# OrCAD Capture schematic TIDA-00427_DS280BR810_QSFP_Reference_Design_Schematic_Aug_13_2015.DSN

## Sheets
1 1. NOTES: title: TIDA-00427 DS280BR810 QSFP Reference Design; rev: 1
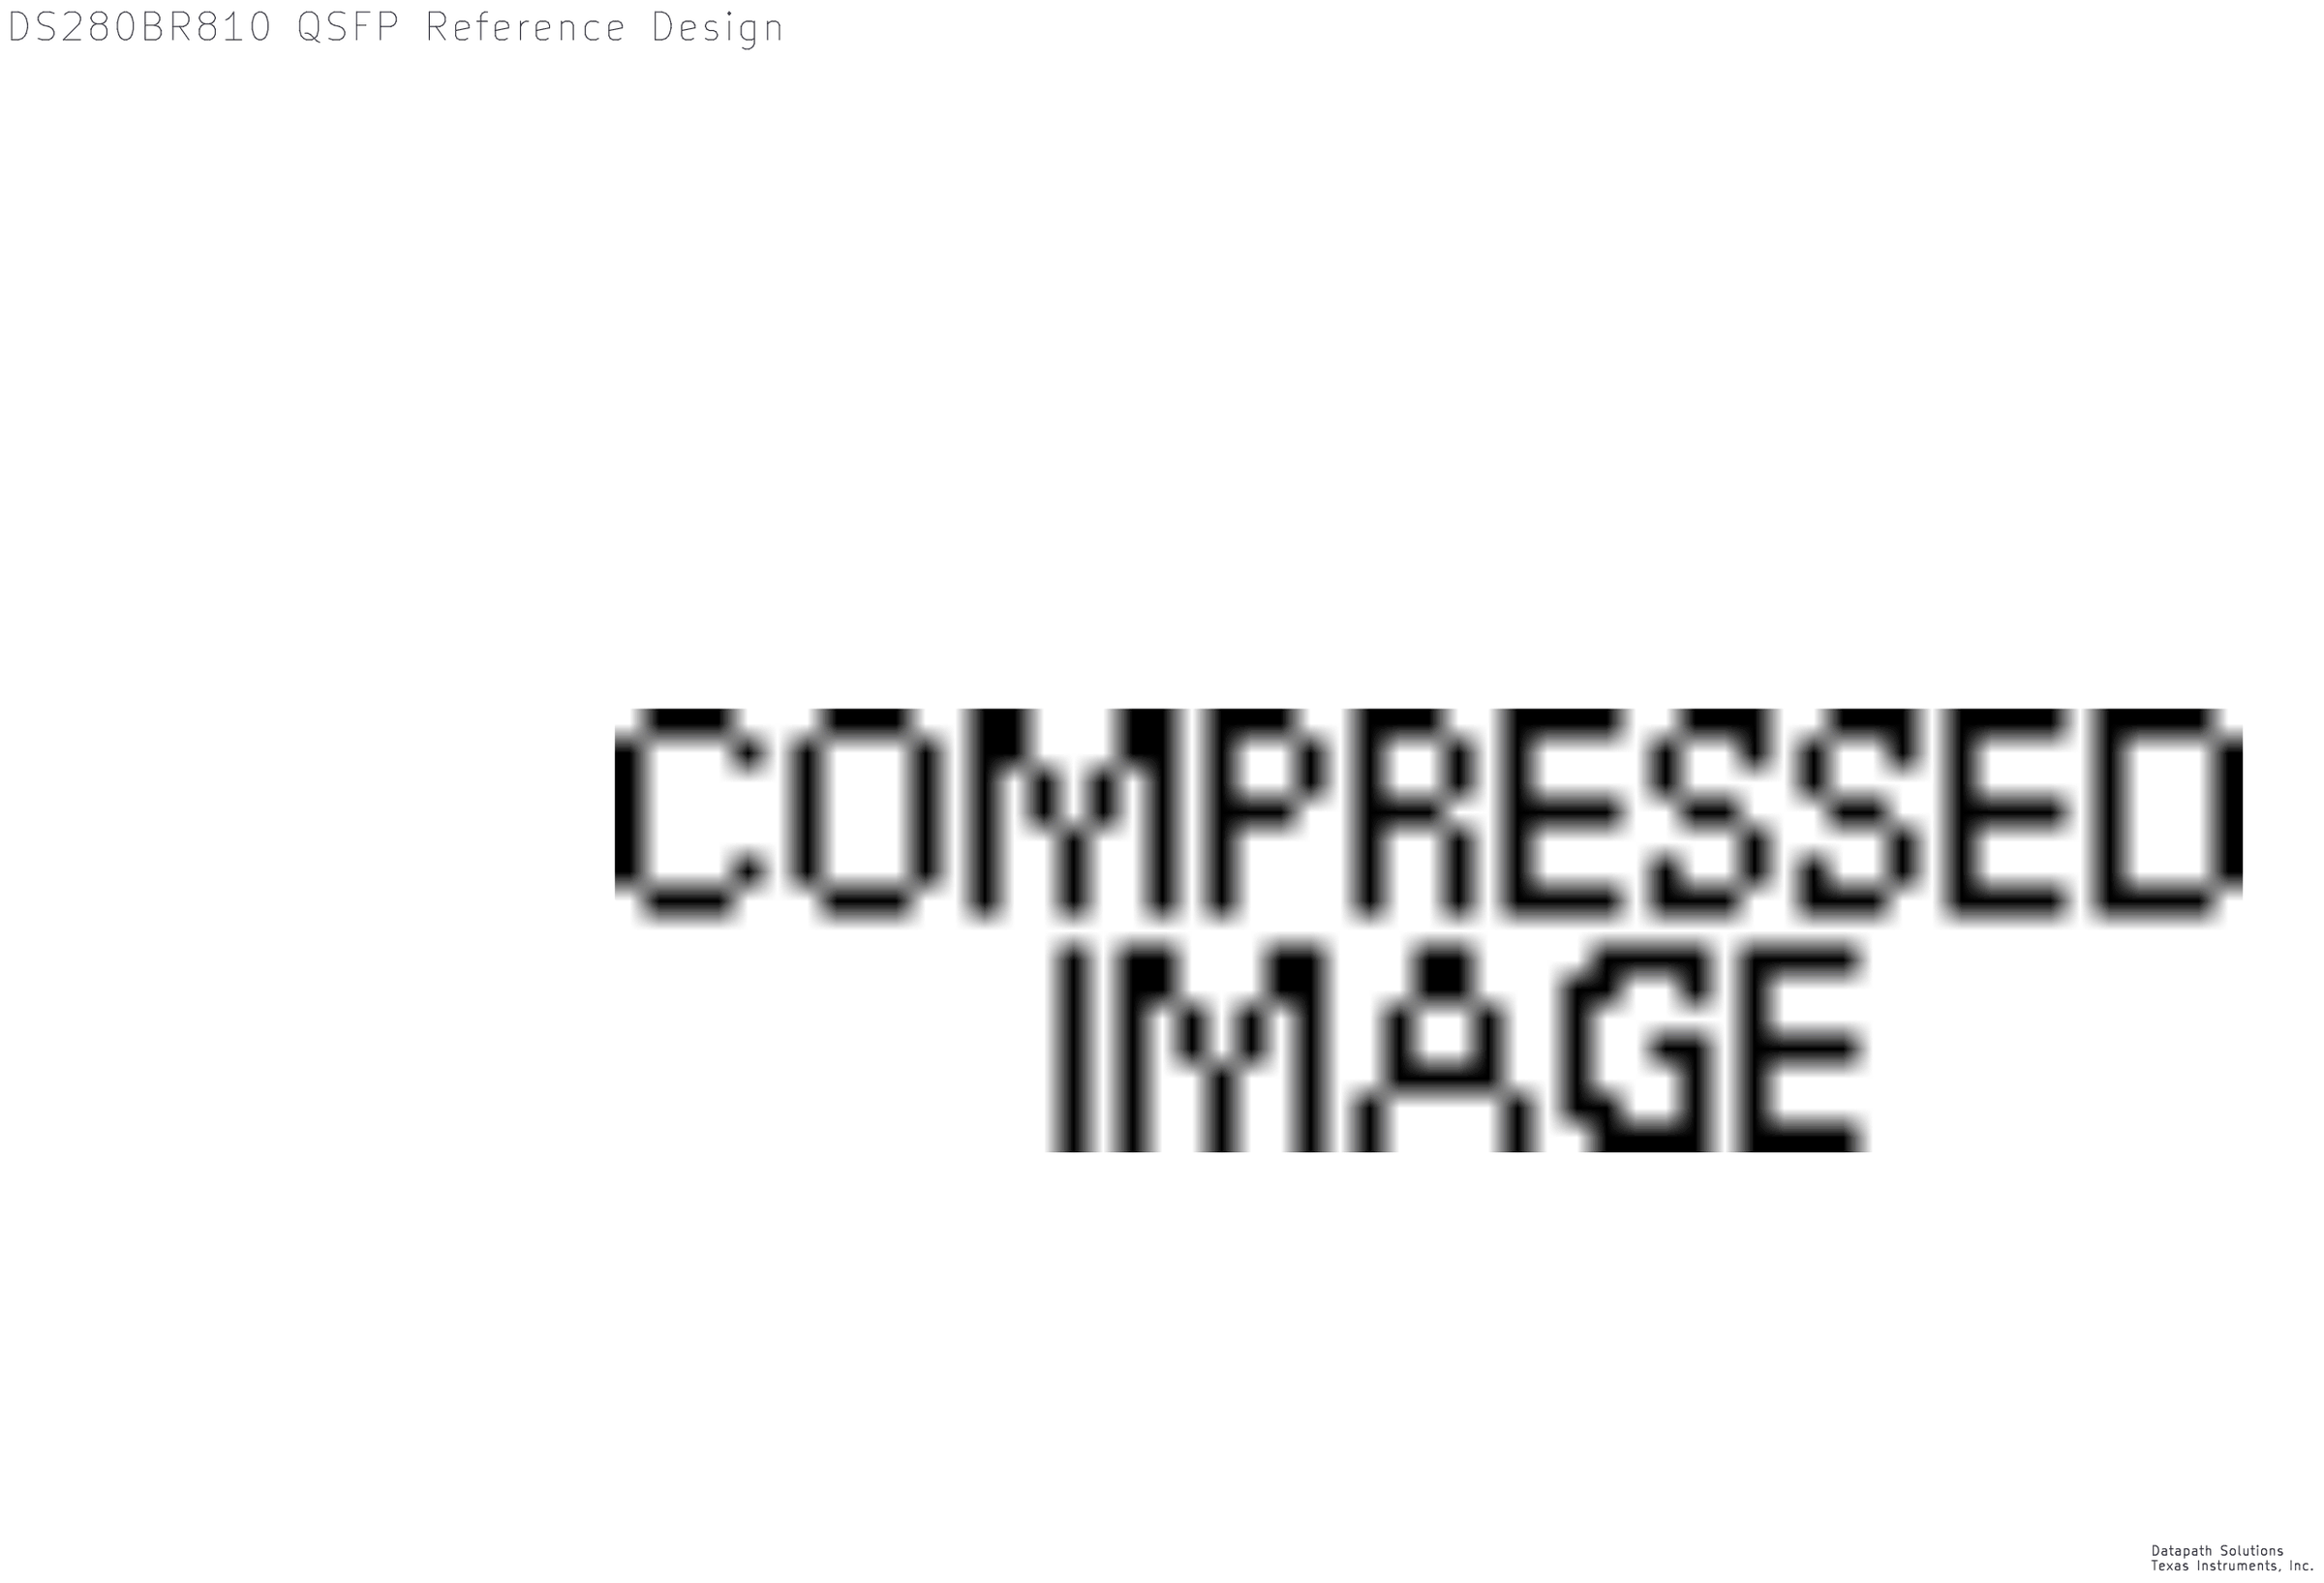
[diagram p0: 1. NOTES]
2 2. DS280BR810_CABLE_2_HOST: size C; note: 305-PD-14-0660
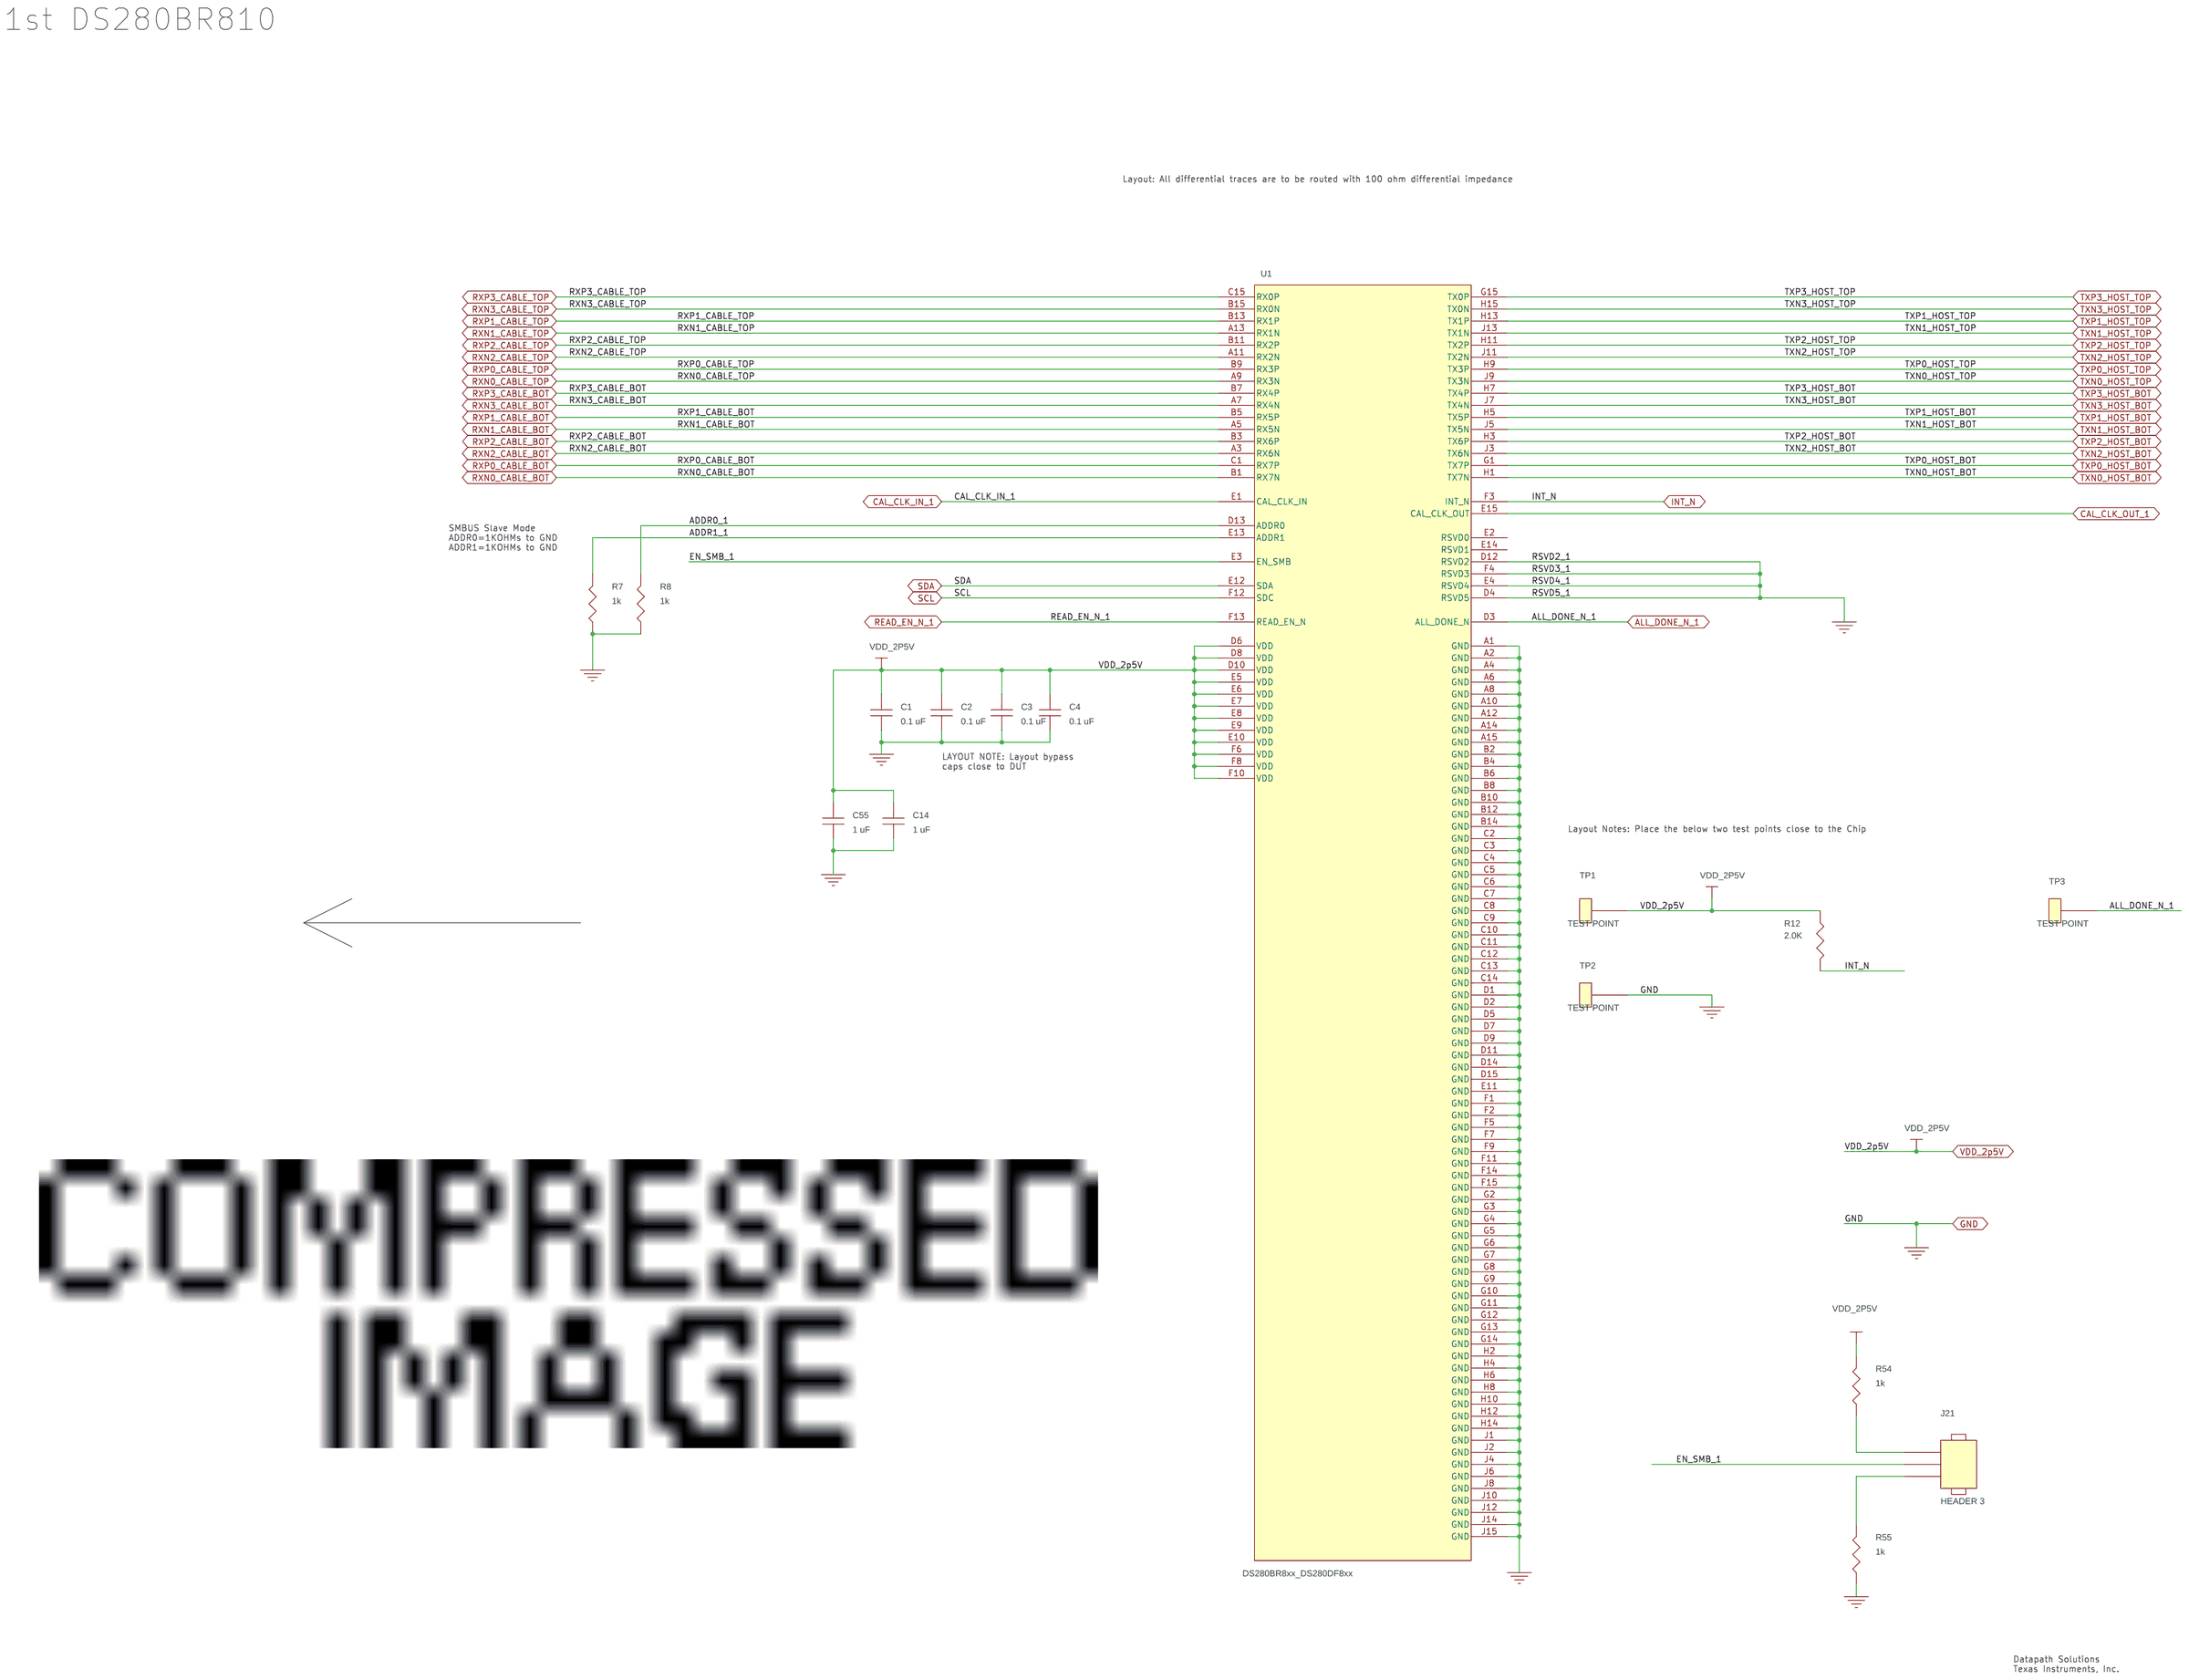
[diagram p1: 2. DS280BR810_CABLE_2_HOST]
3 3. DS280BR810_HOST_2_CABLE: size C; note: 305-PD-14-0660
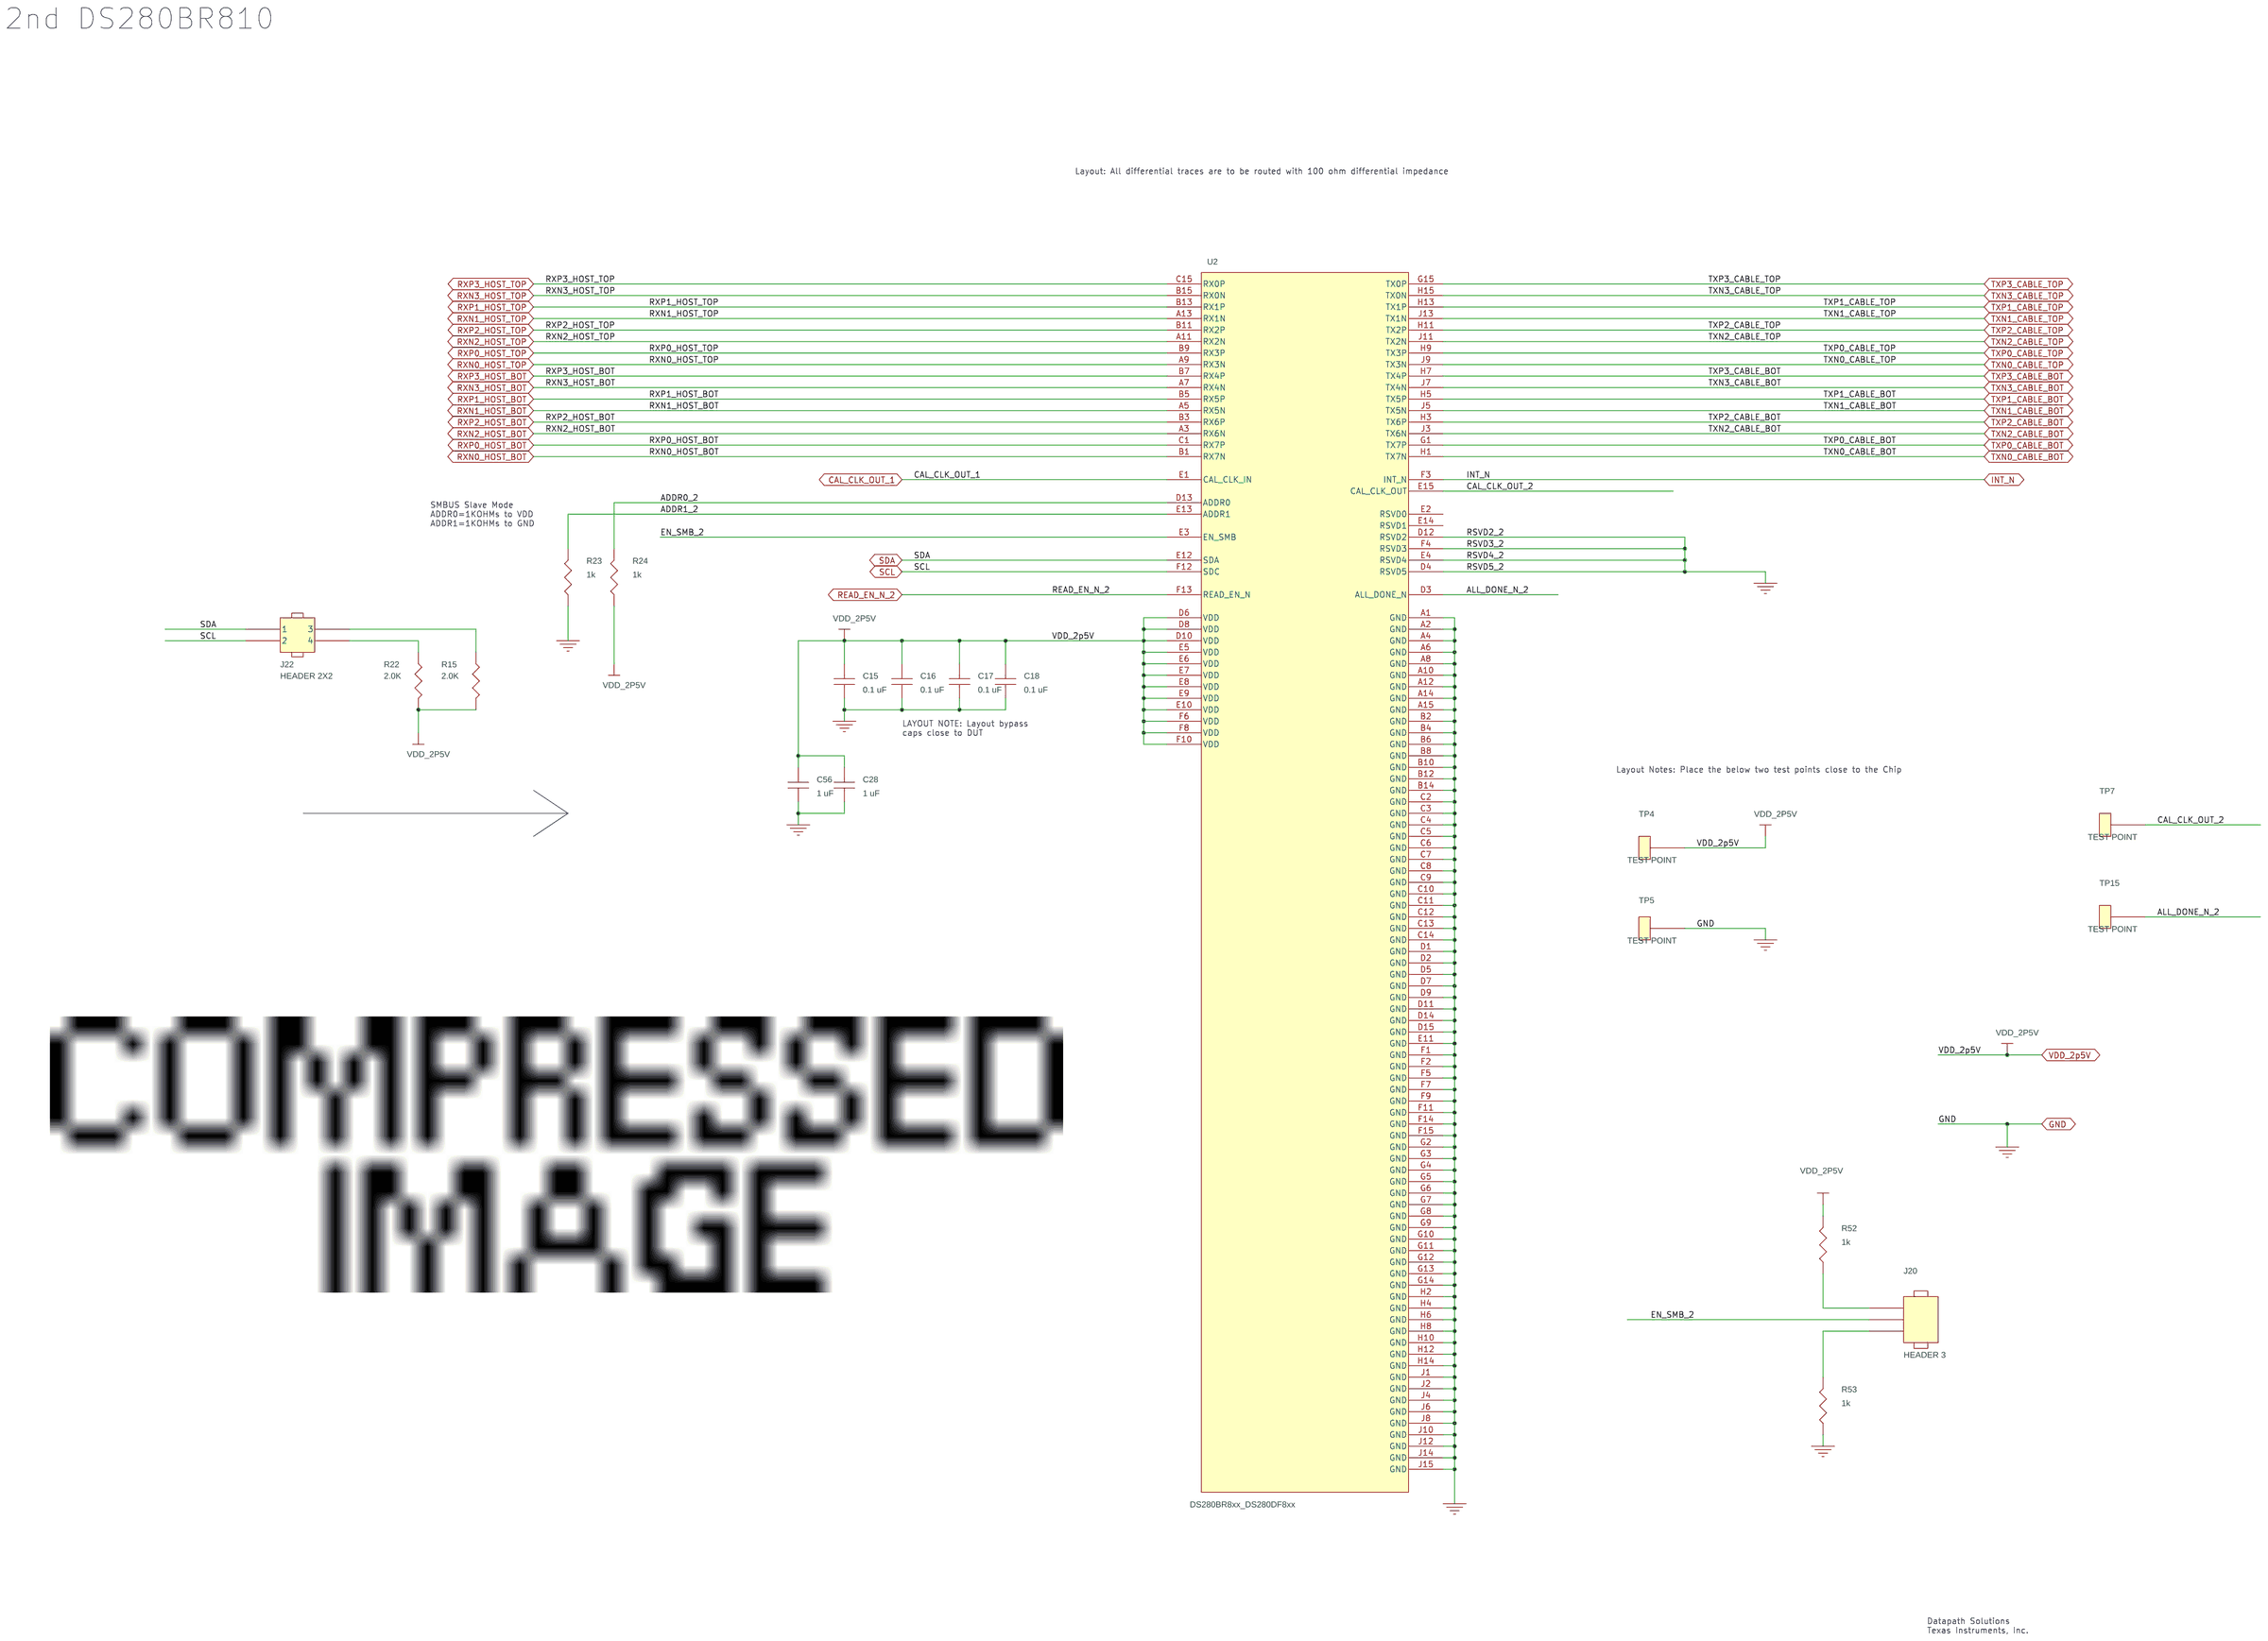
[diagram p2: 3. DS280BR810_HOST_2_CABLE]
4 4. USB2ANY: size B; note: 305-PD-14-0660
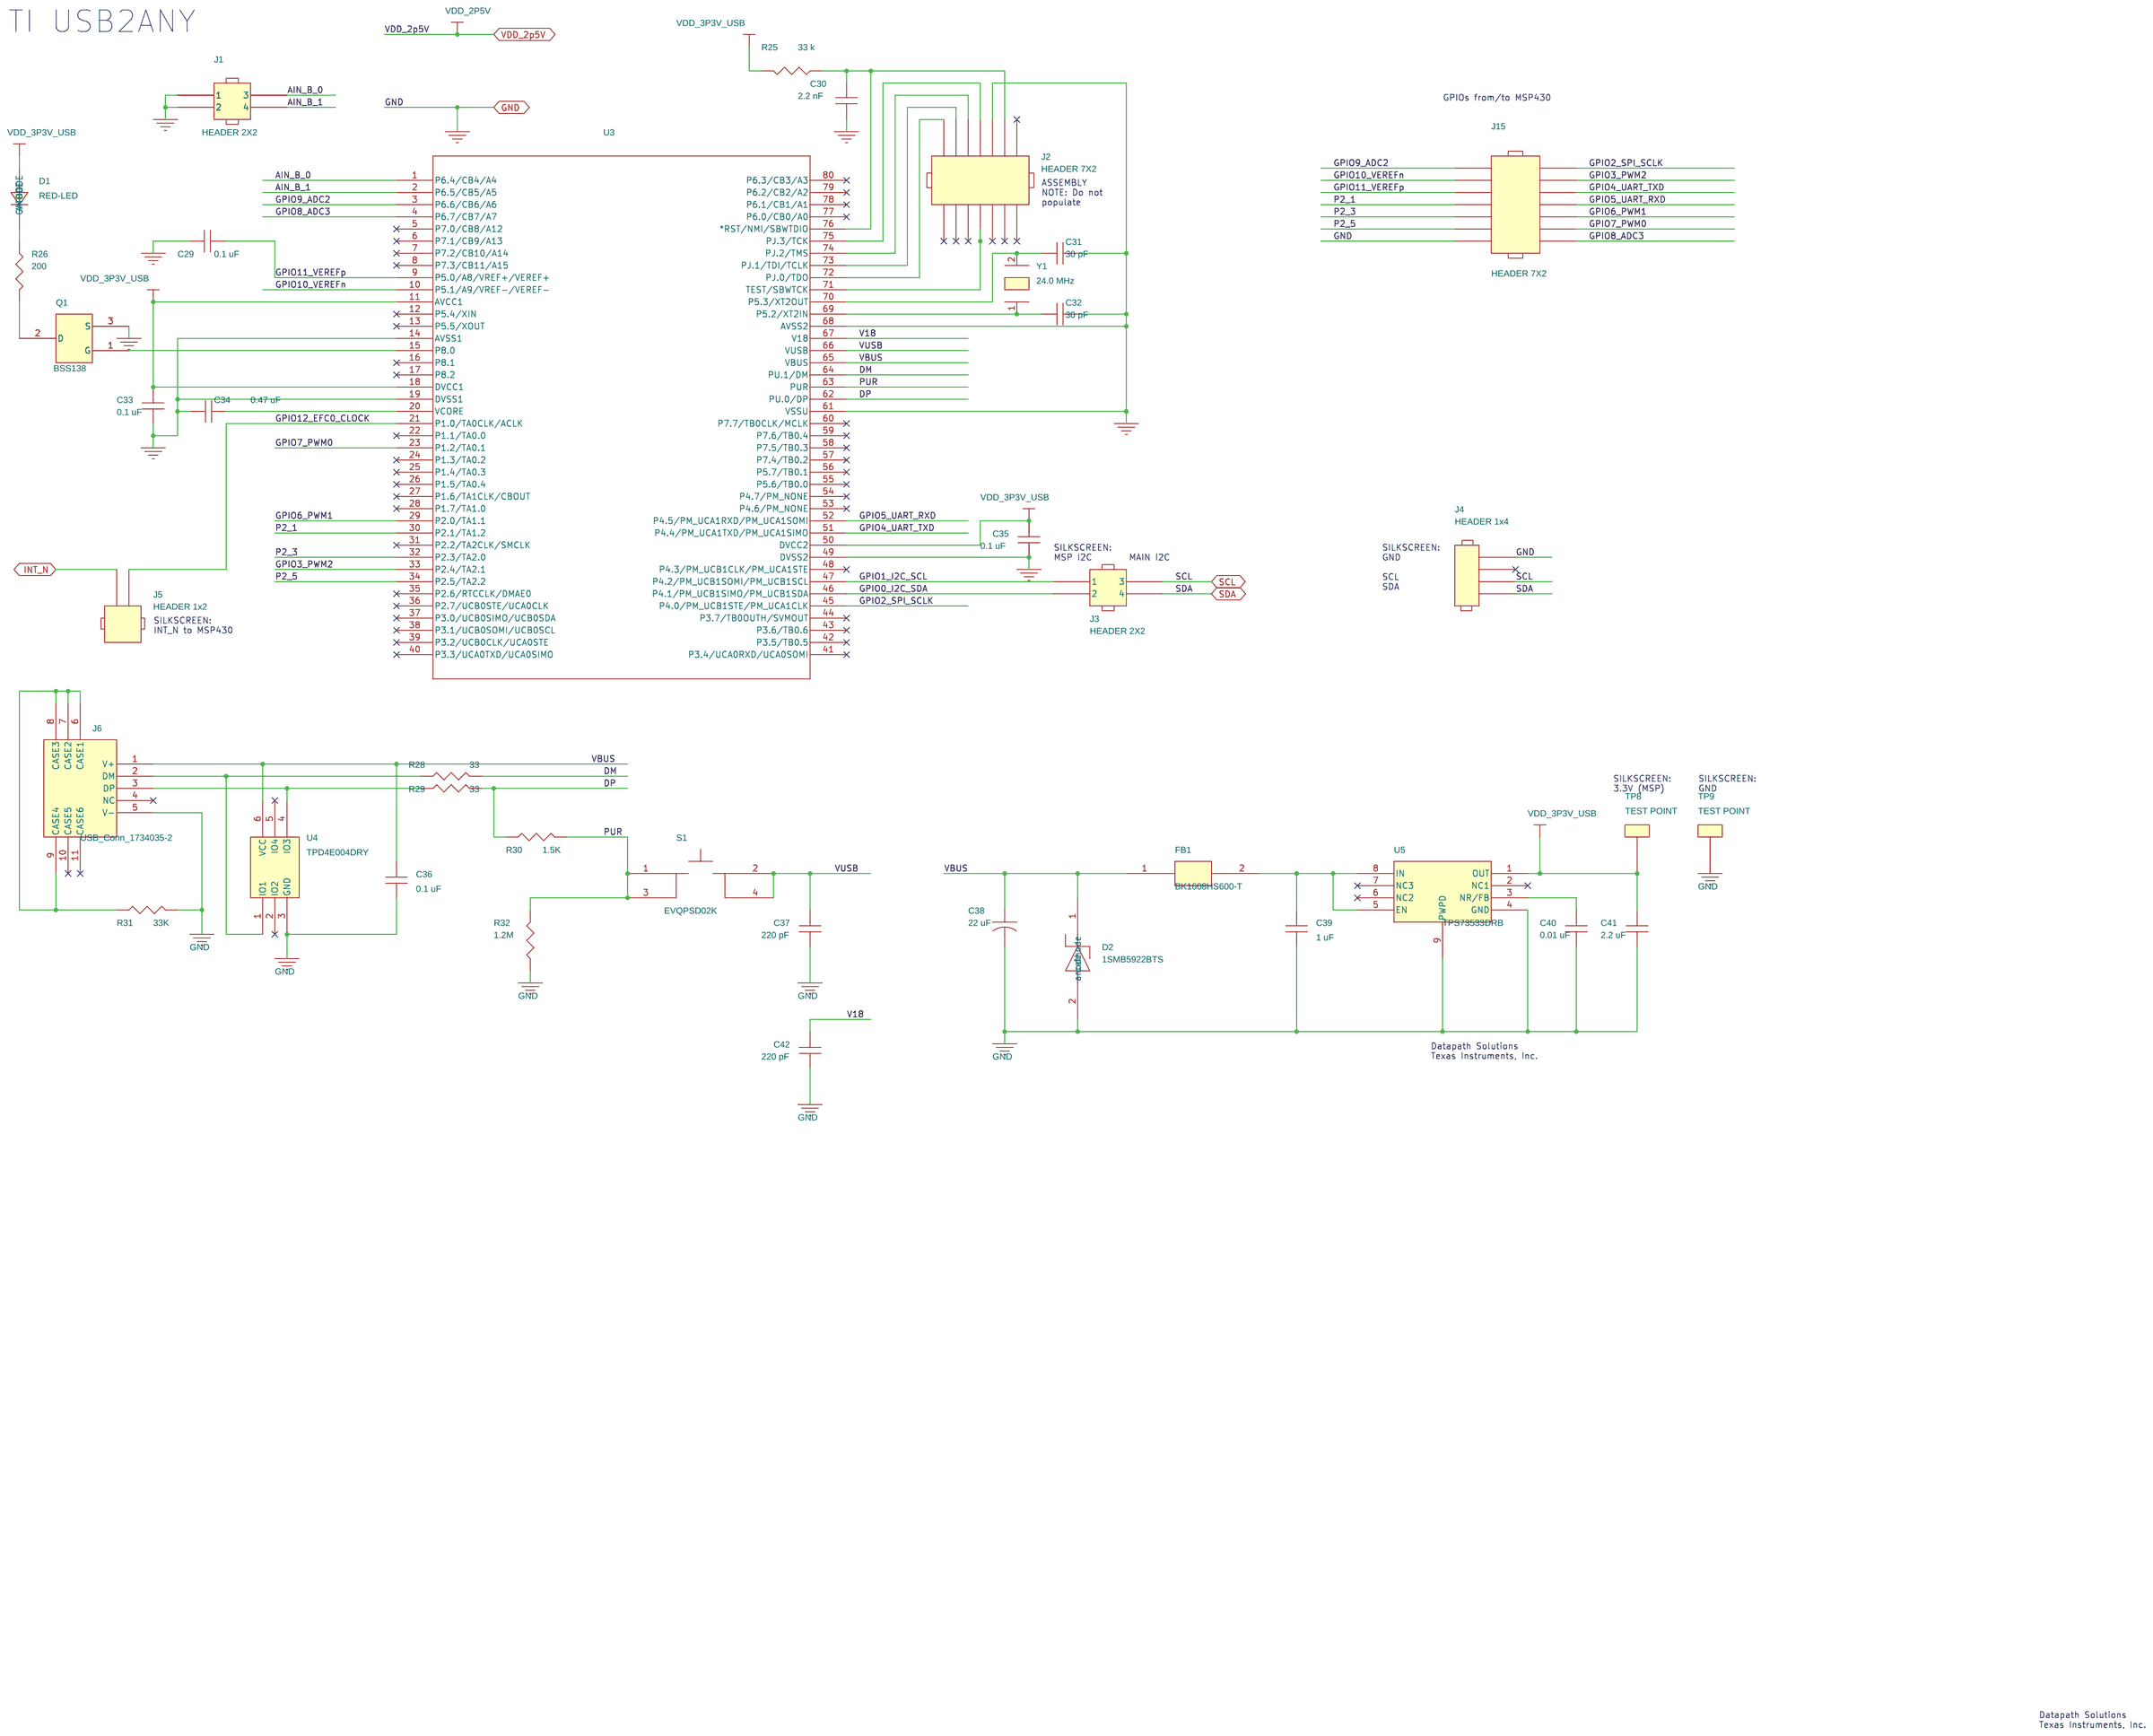
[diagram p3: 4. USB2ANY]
5 5. CAL_CLK_POWER: size B; title: DS280DF810 EVM; note: 305-PD-14-0660
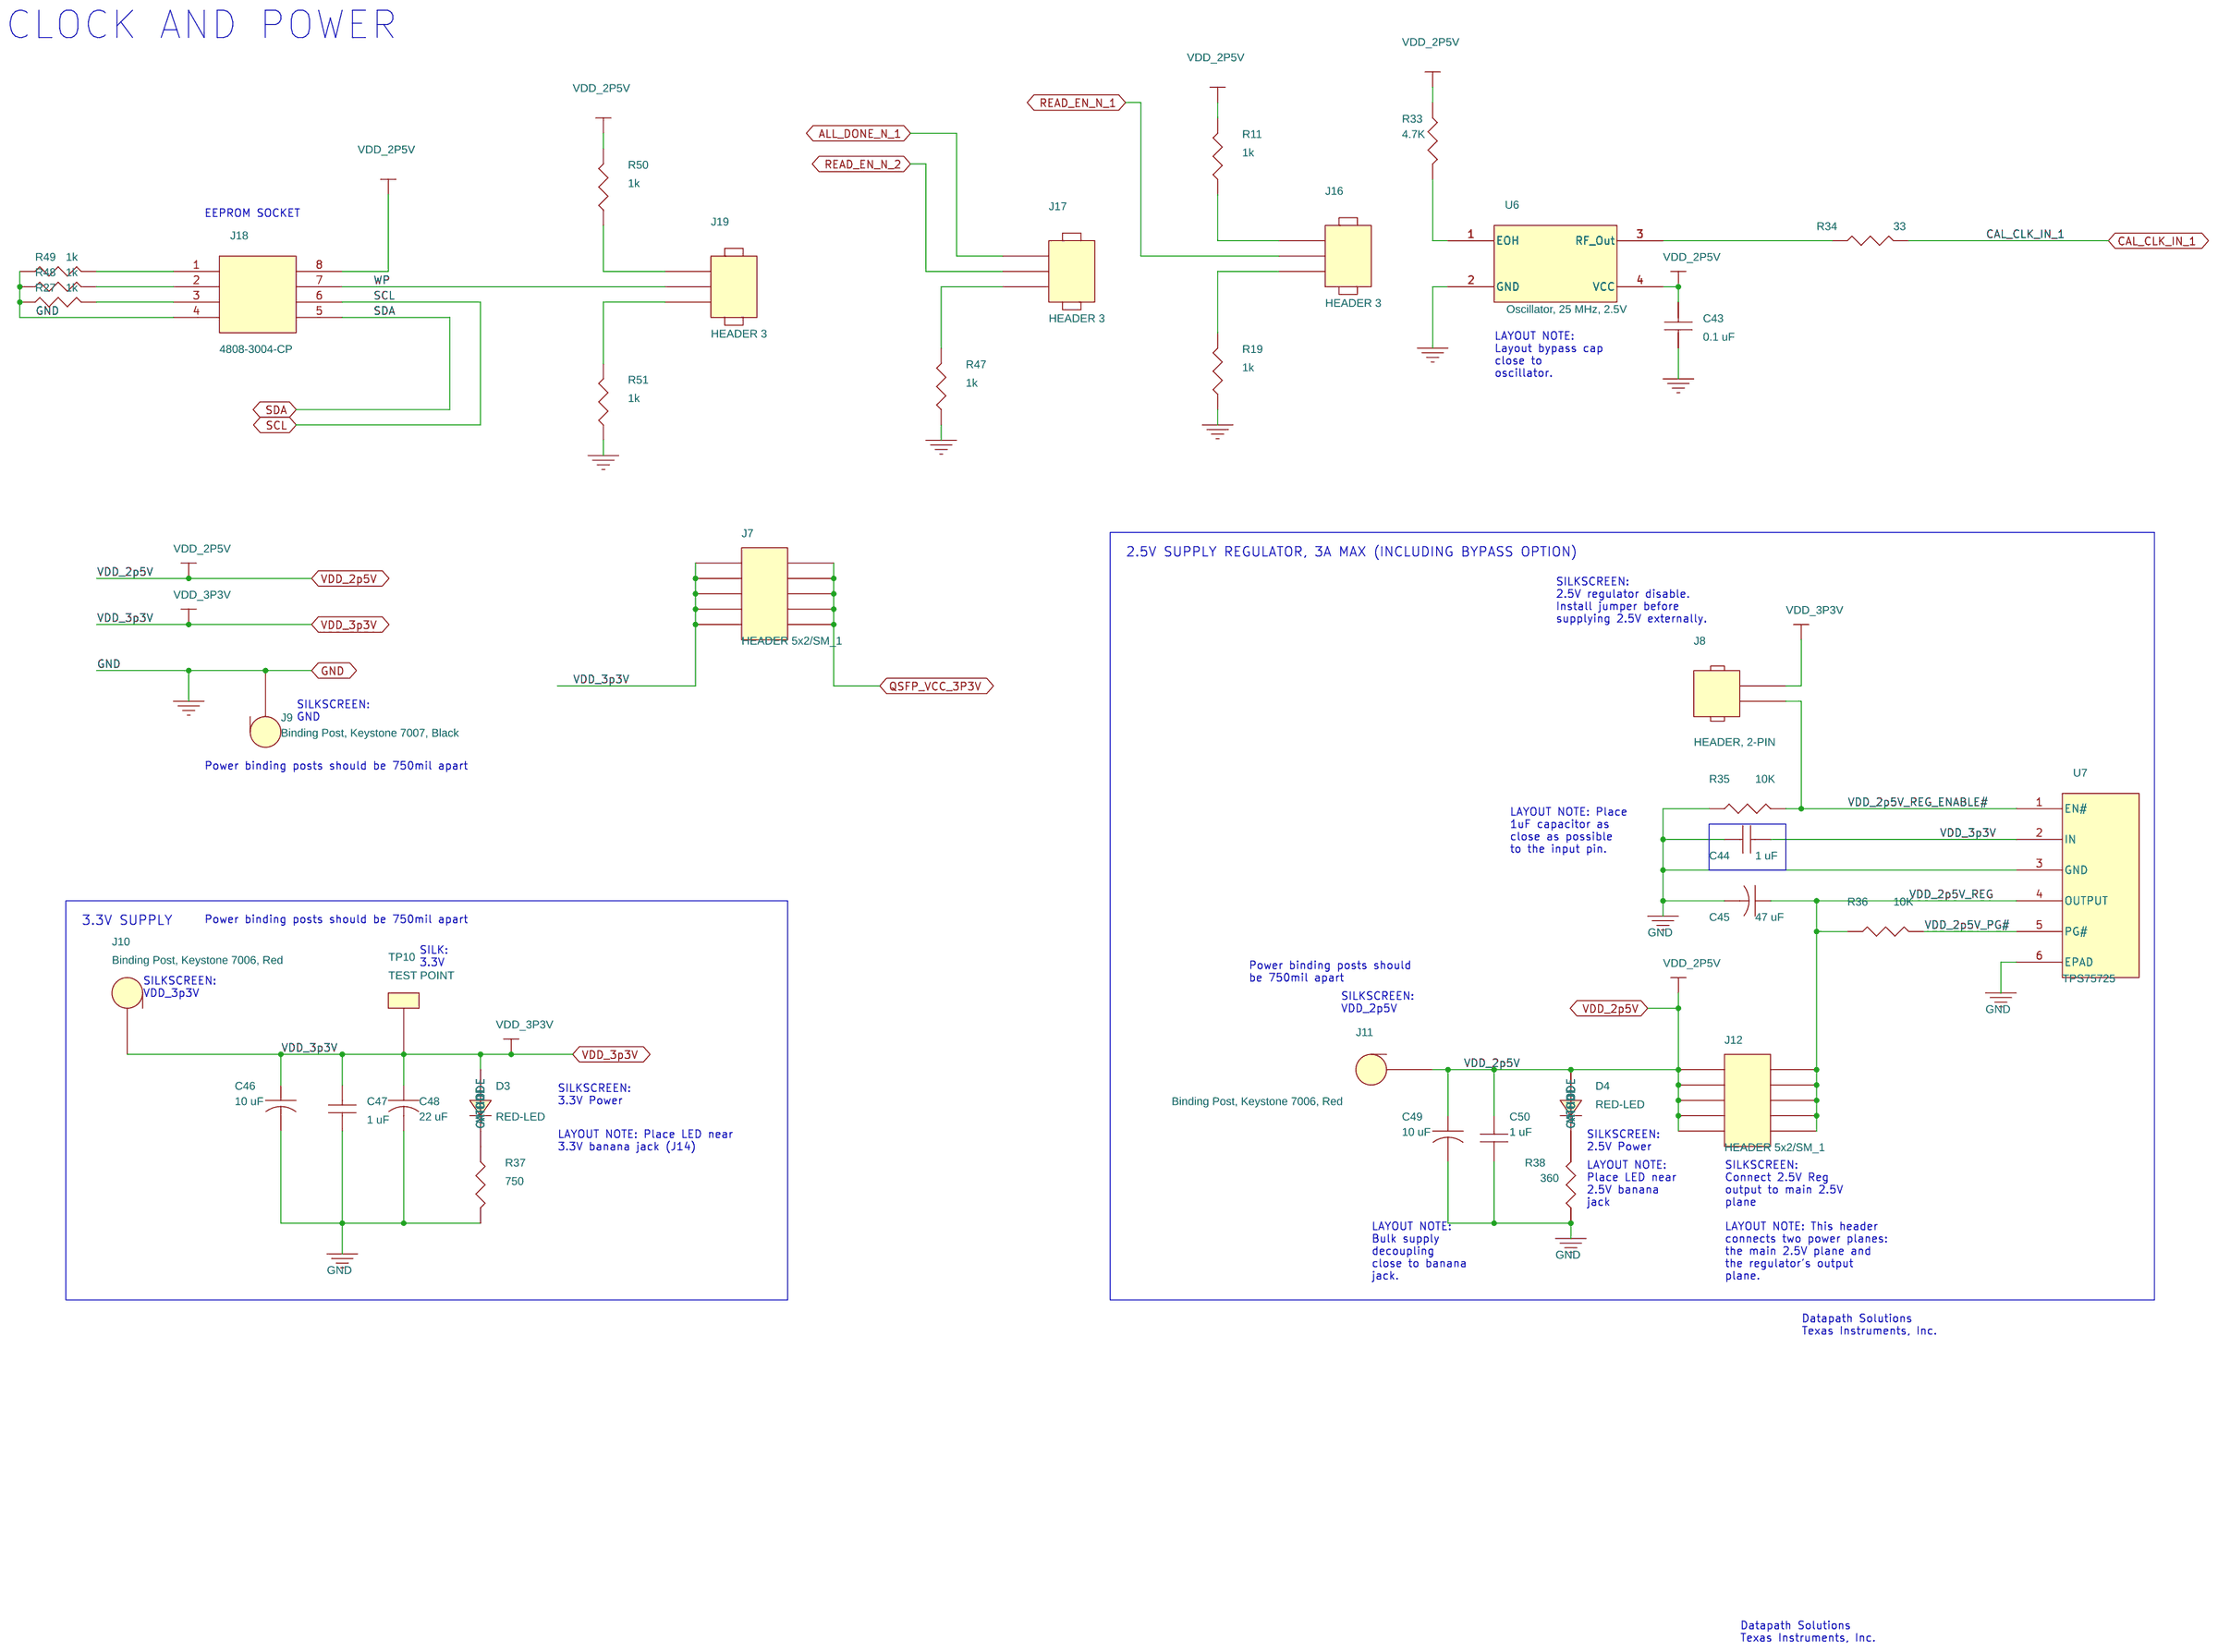
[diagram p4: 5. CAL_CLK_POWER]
6 6. QSFP28 HOST: size B; note: 305-PD-14-0660
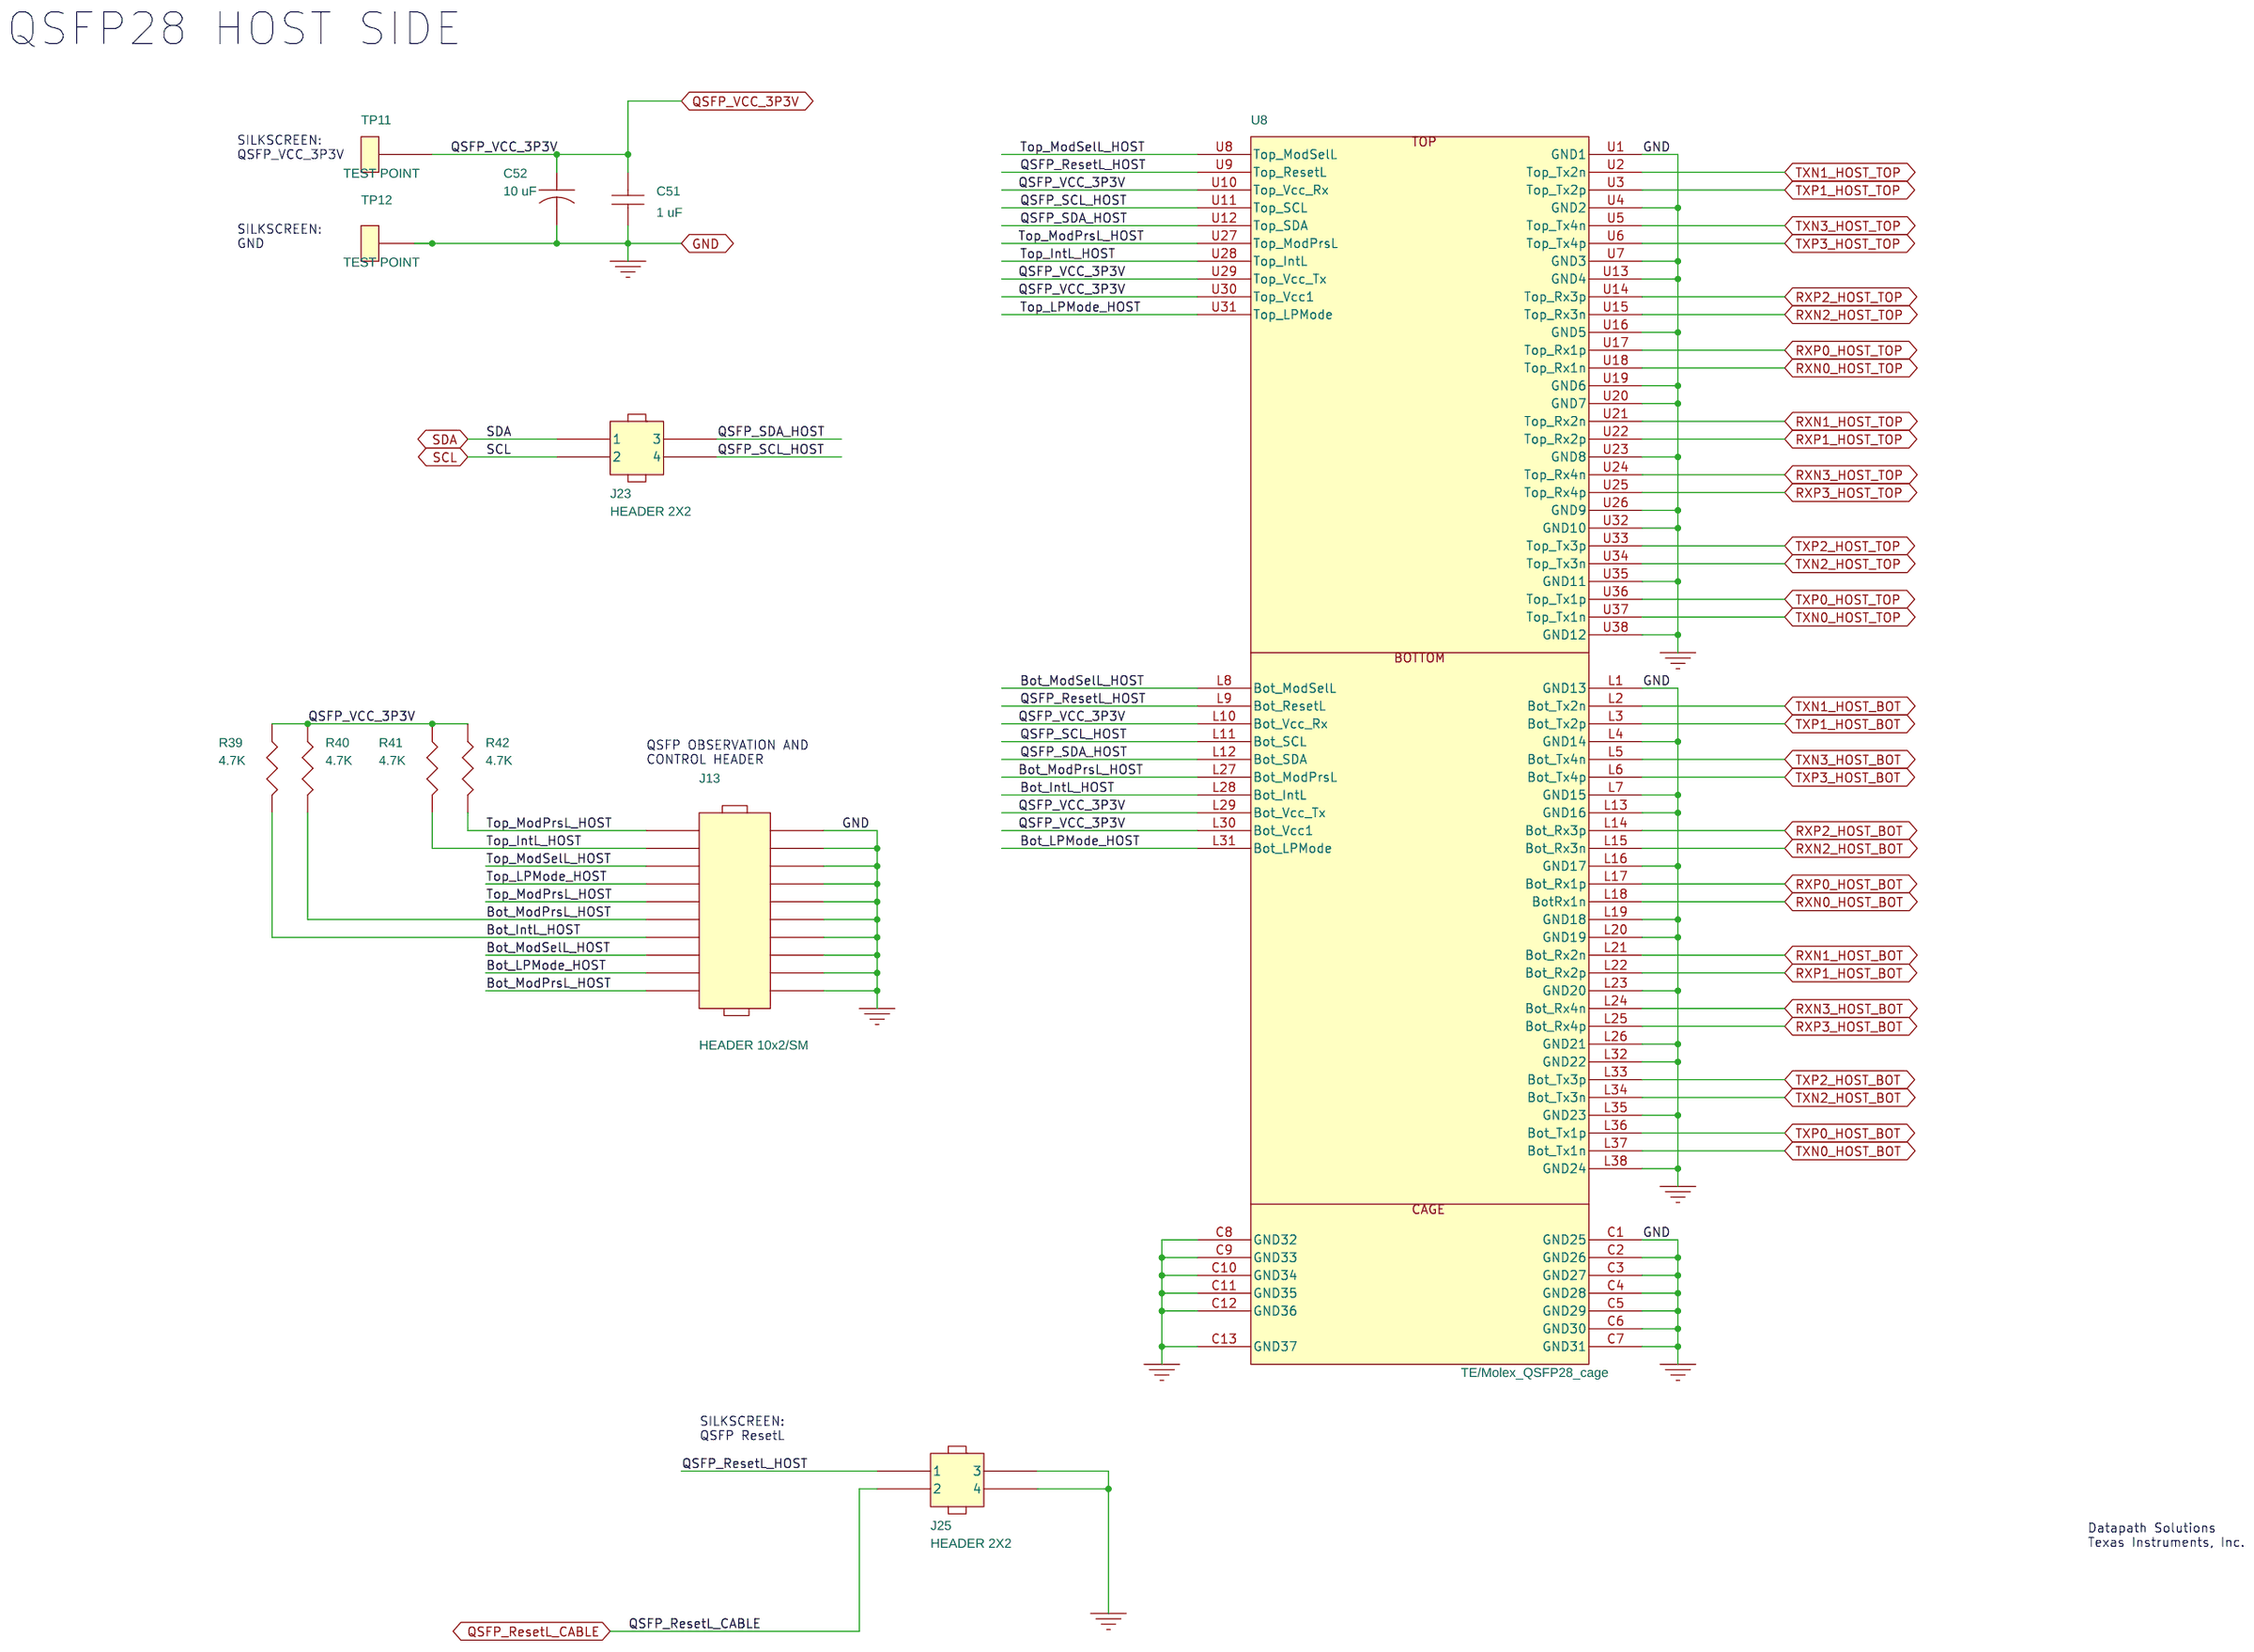
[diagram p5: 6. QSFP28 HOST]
7 7. QSFP28 CABLE: size B; note: 305-PD-14-0660
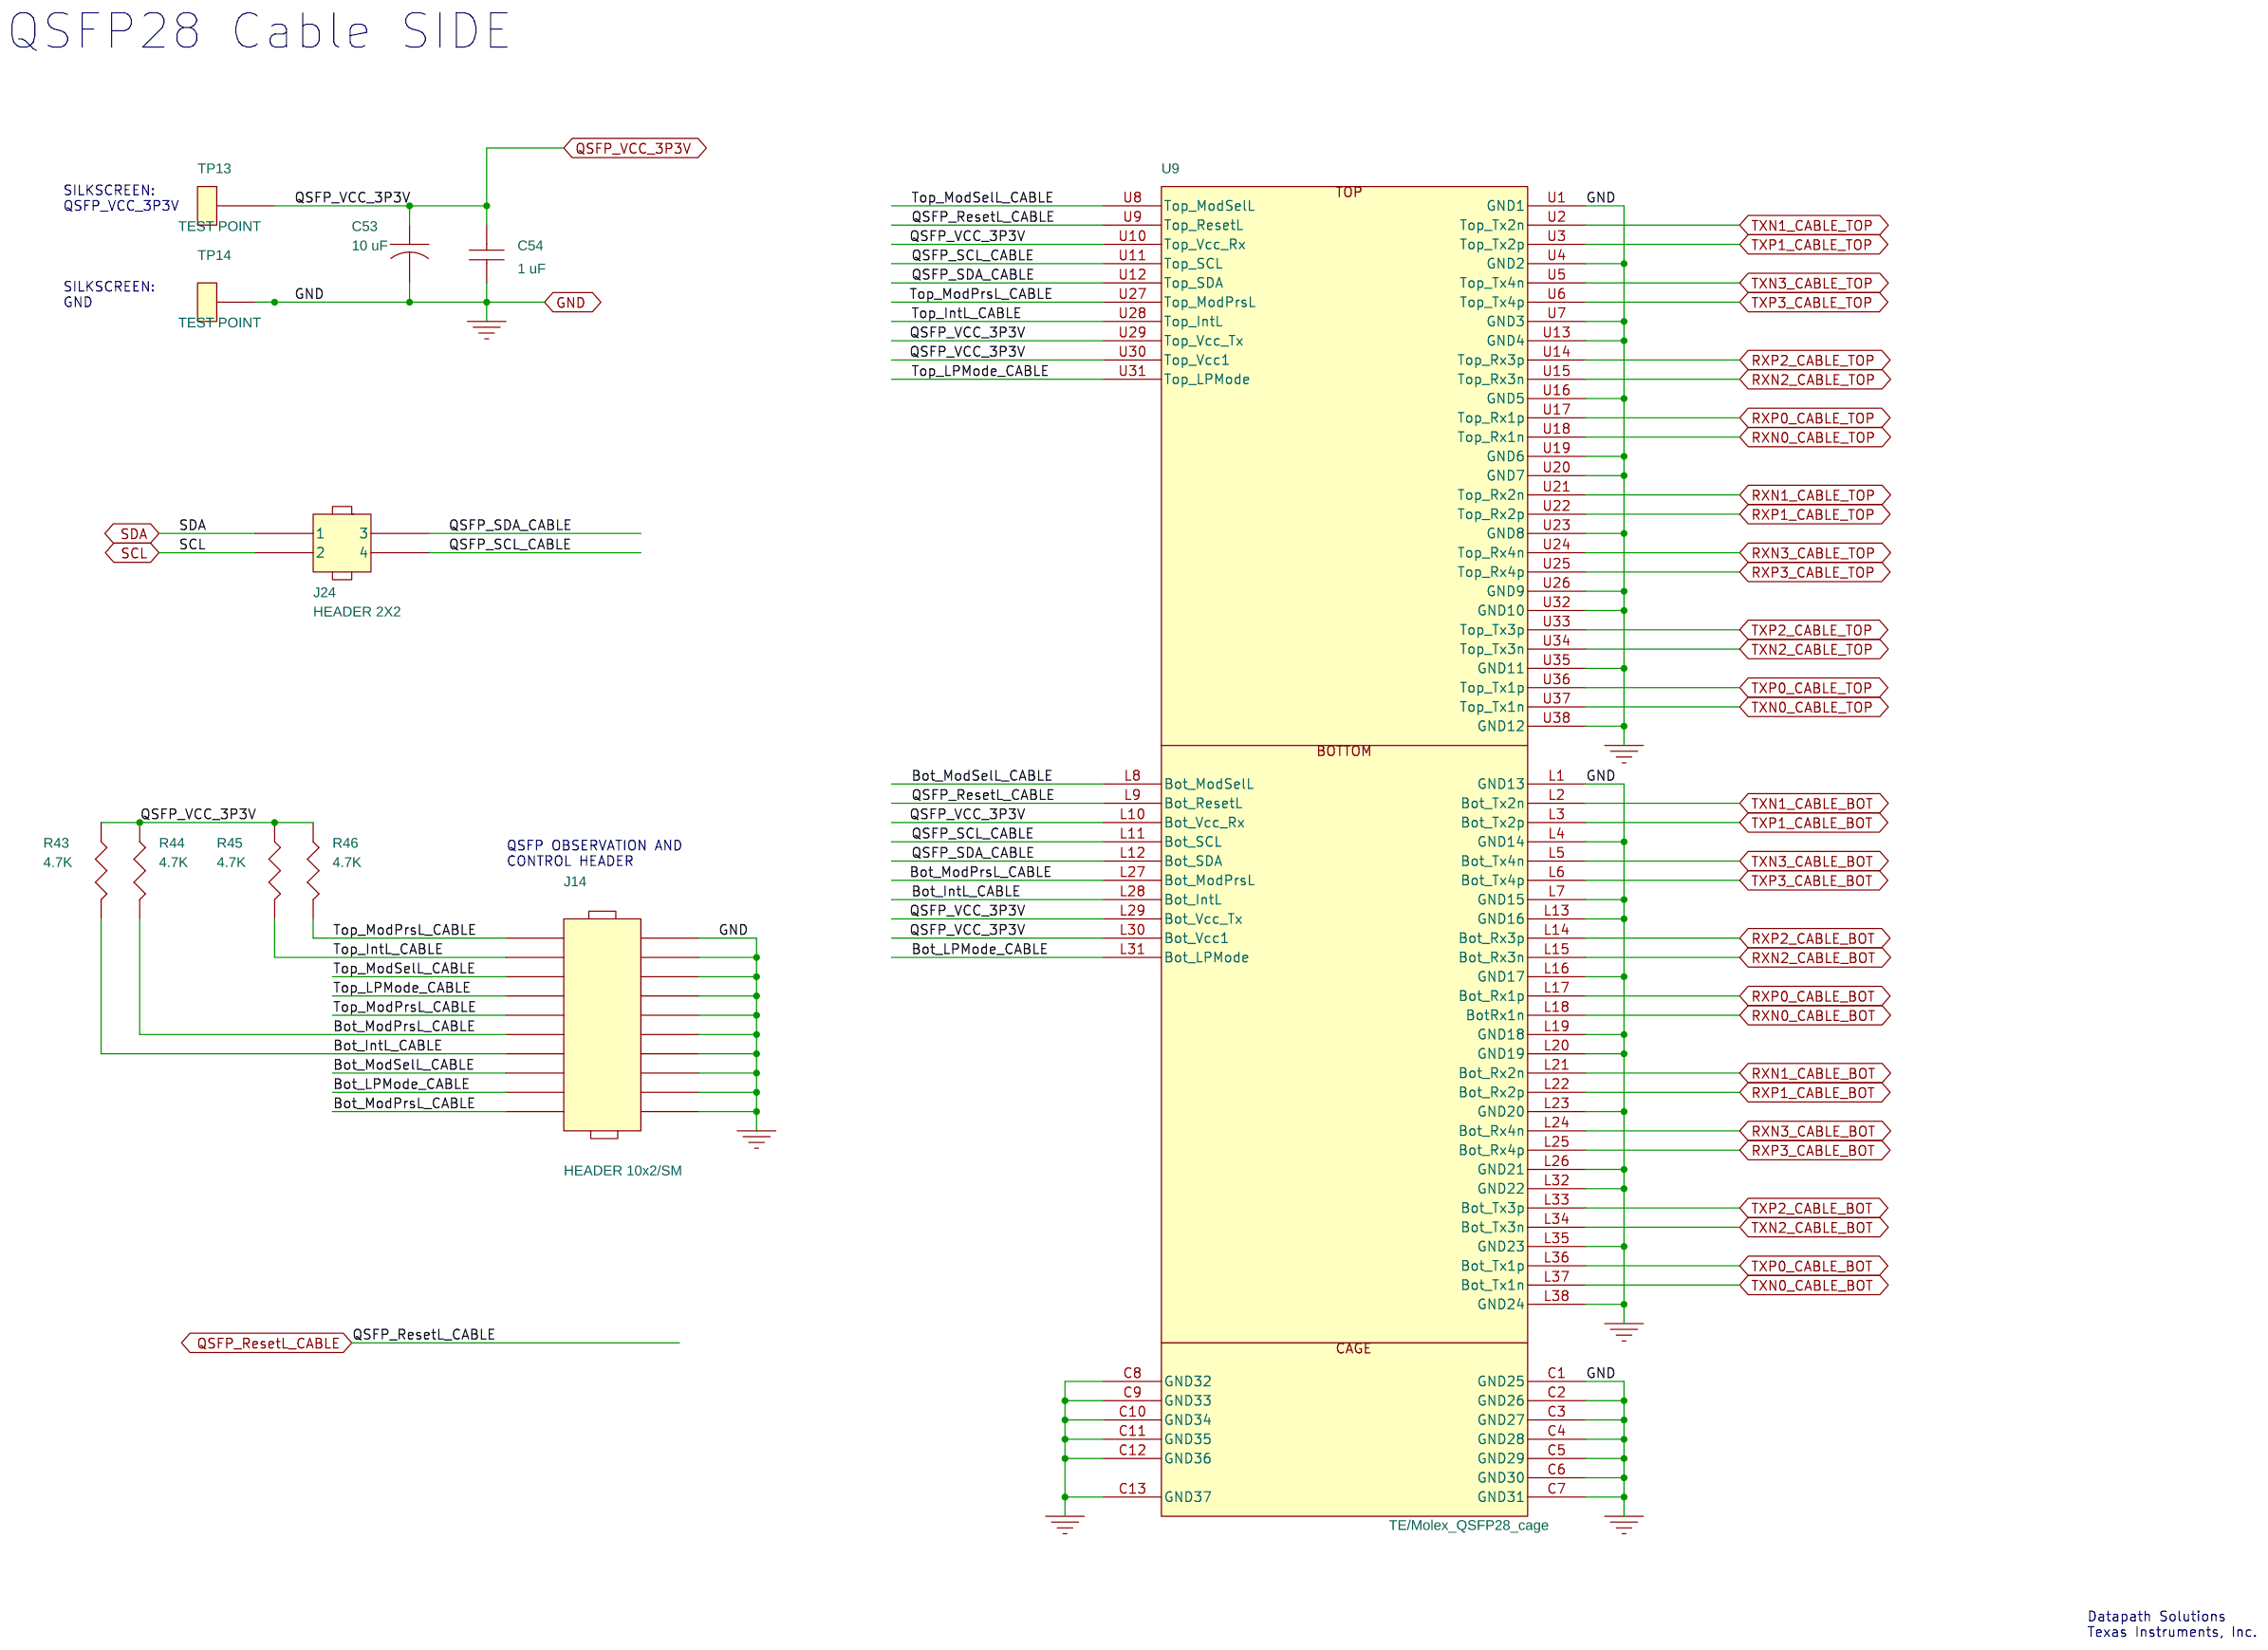
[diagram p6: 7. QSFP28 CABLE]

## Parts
sheet 2. DS280BR810_CABLE_2_HOST
C1  0.1 uF  [C_0402]
C2  0.1 uF  [C_0402]
C3  0.1 uF  [C_0402]
C4  0.1 uF  [C_0402]
C14  1 uF  [C_0402]
C55  1 uF  [C_0402]
J21  HEADER 3  [3_HEADER]
R7  1k  [0402]
R8  1k  [0402]
R12  2.0K  [RR0603]
R54  1k  [0402]
R55  1k  [0402]
TP1  TEST POINT  [0_100x0_100_inch]
TP2  TEST POINT  [0_100x0_100_inch]
TP3  TEST POINT  [0_100x0_100_inch]
U1  DS280BR8xx_DS280DF8xx  [ds280br8xx_ds280df8xx]
sheet 3. DS280BR810_HOST_2_CABLE
C15  0.1 uF  [C_0402]
C16  0.1 uF  [C_0402]
C17  0.1 uF  [C_0402]
C18  0.1 uF  [C_0402]
C28  1 uF  [C_0402]
C56  1 uF  [C_0402]
J20  HEADER 3  [3_HEADER]
J22  HEADER 2X2  [HEADER_2X2]
R15  2.0K  [RR0603]
R22  2.0K  [RR0603]
R23  1k  [0402]
R24  1k  [0402]
R52  1k  [0402]
R53  1k  [0402]
TP4  TEST POINT  [0_100x0_100_inch]
TP5  TEST POINT  [0_100x0_100_inch]
TP7  TEST POINT  [0_100x0_100_inch]
TP15  TEST POINT  [0_100x0_100_inch]
U2  DS280BR8xx_DS280DF8xx  [ds280br8xx_ds280df8xx]
sheet 4. USB2ANY
C29  0.1 uF  [C_0402]
C30  2.2 nF  [C_0603]
C31  30 pF  [C_0603]
C32  30 pF  [C_0603]
C33  0.1 uF  [C_0402]
C34  0.47 uF  [C_0603]
C35  0.1 uF  [C_0402]
C36  0.1 uF  [C_0402]
C37  220 pF  [C_0603]
C38  22 uF  [Code_B]
C39  1 uF  [C_0603]
C40  0.01 uF  [C_0603]
C41  2.2 uF  [C_0805]
C42  220 pF  [C_0603]
D1  RED-LED  [led_footprint]
D2  1SMB5922BTS  [SMB]
FB1  BK1608HS600-T  [FB0603]
J1  HEADER 2X2  [HEADER_2X2]
J2  HEADER 7X2  [HEADER_7X2]
J3  HEADER 2X2  [HEADER_2X2]
J4  HEADER 1x4  [4_HEADER]
J5  HEADER 1x2  [cn-hdr1x2]
J6  USB_Conn_1734035-2  [1734035-2]
J15  HEADER 7X2  [HEADER_7X2]
Q1  BSS138  [SOT-23]
R25  33 k  [R_0402]
R26  200  [RES_HDC-0603]
R28  33  [RES_HDC-0402]
R29  33  [RES_HDC-0402]
R30  1.5K  [RES_HDC-0402]
R31  33K  [RES_HDC-0402]
R32  1.2M  [RES_HDC-0402]
S1  EVQPSD02K  [EVQPSD02K]
TP8  TEST POINT  [0_100x0_100_inch]
TP9  TEST POINT  [0_100x0_100_inch]
U3  Value  [PN80]
U4  TPD4E004DRY  [SON-6]
U5  TPS73533DRB  [SON-8]
Y1  24.0 MHz  [HC49_US]
sheet 5. CAL_CLK_POWER
C43  0.1 uF  [C_0402]
C44  1 uF  [C_0603]
C45  47 uF  [c_1210]
C46  10 uF  [C_0805_TANT]
C47  1 uF  [C_0603]
C48  22 uF  [c_sizec]
C49  10 uF  [C_0805_TANT]
C50  1 uF  [C_0603]
D3  RED-LED  [led_footprint]
D4  RED-LED  [led_footprint]
J7  HEADER 5x2/SM_1  [cn-hdr2x5]
J8  HEADER, 2-PIN  [cn-hdr1x2]
J9  Binding Post, Keystone 7007, Black  [cn-bananajk-275-interface]
J10  Binding Post, Keystone 7006, Red  [cn-bananajk]
J11  Binding Post, Keystone 7006, Red  [cn-bananajk]
J12  HEADER 5x2/SM_1  [cn-hdr2x5]
J16  HEADER 3  [3_HEADER]
J17  HEADER 3  [3_HEADER]
J18  4808-3004-CP  [DIP8]
J19  HEADER 3  [3_HEADER]
R11  1k  [0402]
R19  1k  [0402]
R27  1k  [0402]
R33  4.7K  [R_0402]
R34  33  [RES_HDC-0402]
R35  10K  [R_0402]
R36  10K  [R_0402]
R37  750  [RES_HDC-0603]
R38  360  [RES_HDC-0603]
R47  1k  [0402]
R48  1k  [0402]
R49  1k  [0402]
R50  1k  [0402]
R51  1k  [0402]
TP10  TEST POINT  [0_100x0_100_inch]
U6  Oscillator, 25 MHz, 2.5V  [txc_2v5_osc]
U7  TPS75725  [TO-263]
sheet 6. QSFP28 HOST
C51  1 uF  [C_0603]
C52  10 uF  [C_0805_TANT]
J13  HEADER 10x2/SM  [HEADER_10x2_SM]
J23  HEADER 2X2  [HEADER_2X2]
J25  HEADER 2X2  [HEADER_2X2]
R39  4.7K  [R_0402]
R40  4.7K  [R_0402]
R41  4.7K  [R_0402]
R42  4.7K  [R_0402]
TP11  TEST POINT  [0_100x0_100inch]
TP12  TEST POINT  [0_100x0_100inch]
U8  TE/Molex_QSFP28_cage  [Molex_zQSFP_cage]
sheet 7. QSFP28 CABLE
C53  10 uF  [C_0805_TANT]
C54  1 uF  [C_0603]
J14  HEADER 10x2/SM  [HEADER_10x2_SM]
J24  HEADER 2X2  [HEADER_2X2]
R43  4.7K  [R_0402]
R44  4.7K  [R_0402]
R45  4.7K  [R_0402]
R46  4.7K  [R_0402]
TP13  TEST POINT  [0_100x0_100inch]
TP14  TEST POINT  [0_100x0_100inch]
U9  TE/Molex_QSFP28_cage  [Molex_zQSFP_cage]

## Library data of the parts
C1-C4 C15-C18 C29 C33 C35 C36 C43 = CAP_NP: Comment: CAP CER 0.1UF 16V 10% X7R 0402; Comments: CAP CER 0.1UF 16V 10% X7R 0402; Digi-Key P/N: 490-3261-1-ND; Digikey P/N: 490-3261-1-ND; Distributor: Digi-Key; Distributor Part Number: 490-3261-1-ND; Distributor_Part_Number: 490-3261-1-ND; Lead Free?: YES; Manufacturer: Murata Electronics North America; Manufacturer P/N: GRM155R71C104KA88D; Manufacturer_Part_Number: GRM155R71C104KA88D; Part number: GRM155R71C104KA88D; PartNumber: GRM155R71C104KA88D; ROHS Compliant?: YES; Tolerance: 10%; Vendor: Murata Electronics North America; size: 402
C14 C28 C55 C56 = CAPACITOR_NON-POL: Comment: CAP CER 1UF 6.3V 10% X7R 0402; Comments: CAP CER 1UF 6.3V 10% X7R 0402; Digi-Key P/N: 311-1702-2-ND; Digikey P/N: 311-1702-2-ND; Distributor: Digi-Key; Distributor Part Number: 311-1702-2-ND; Distributor_Part_Number: 311-1702-2-ND; Lead Free?: YES; Manufacturer: Yageo; Manufacturer P/N: CC0402KRX7R5BB105; Manufacturer_Part_Number: CC0402KRX7R5BB105; Part number: CC0402KRX7R5BB105; PartNumber: CC0402KRX7R5BB105; ROHS Compliant?: YES; Rating: 10V; Tolerance: -20%, +80%; VOLTAGE: 6.3V; Vendor: Yageo; size: 603
J16 J17 J19-J21 = HEADER_3
R7 R8 R11 R19 R23 R24 R27 R47-R55 = RESISTOR
R12 R15 R22 = R: Resistor 2.0K 0603; Manufacturer: Panasonic; Manufacturer's Part#: ERJ3EKF1002V; Part#: eprt-r603-n1002-0000; Status: OK
TP1 TP4 TP7 TP8 TP10 TP11 TP13 TP15 = TEST_POINT: Comment: Test Point,  Red, Thru Hole Color Keyed; Comments: Test Point,  Red, Thru Hole Color Keyed; Manufacturer: Keystone; Manufacturer P/N: 5000
TP2 TP3 TP5 TP9 TP12 TP14 = TEST_POINT: Comment: Test Point,  Black, Thru Hole Color Keyed; Comments: Test Point,  Black, Thru Hole Color Keyed; Manufacturer: Keystone; Manufacturer P/N: 5001
U1 U2 = ds280br8xx_ds280df8xx_1
J1 J3 J22-J25 = HEADER_2X2
C30 = CAP_NP: Comment: Capacitor, Ceramic, 25V, X7R, 20%; Comments: Capacitor, Ceramic, 25V, X7R, 20%; Digi-Key P/N: 399-9041-1-ND; Digikey P/N: 399-9041-1-ND; Distributor: Digi-Key; Distributor Part Number: 399-9041-1-ND; Distributor_Part_Number: 399-9041-1-ND; Lead Free?: YES; Manufacturer: Kemet; Manufacturer P/N: C0603C222M3RACTU; Manufacturer_Part_Number: C0603C222M3RACTU; Part number: C0603C222M3RACTU; PartNumber: C0603C222M3RACTU; ROHS Compliant?: YES; Tolerance: 20%; Vendor: Kemet; size: 603
C31 C32 = CAP_NP: Comment: CAP CER 30PF 50V 5% NP0 0603; Comments: CAP CER 30PF 50V 5% NP0 0603; Digi-Key P/N: 490-1414-1-ND; Digikey P/N: 490-1414-1-ND; Distributor: Digi-Key; Distributor Part Number: 490-1414-1-ND; Distributor_Part_Number: 490-1414-1-ND; Lead Free?: YES; Manufacturer: Murata Electronics North America; Manufacturer P/N: GRM1885C1H300JA01D; Manufacturer_Part_Number: GRM1885C1H300JA01D; Part number: GRM1885C1H300JA01D; PartNumber: GRM1885C1H300JA01D; ROHS Compliant?: YES; Tolerance: 10%; Vendor: Murata; size: 603
C34 = CAP_NP: Comment: CAP CER 0.47UF 16V 10% X7R 0603; Comments: CAP CER 0.47UF 16V 10% X7R 0603; Digi-Key P/N: 587-1250-1-ND; Digikey P/N: 587-1250-1-ND; Distributor: Digi-Key; Distributor Part Number: 587-1250-1-ND; Distributor_Part_Number: 587-1250-1-ND; Lead Free?: YES; Manufacturer: Taiyo Yuden; Manufacturer P/N: EMK107B7474KA-T; Manufacturer_Part_Number: EMK107B7474KA-T; Part number: EMK107B7474KA-T; PartNumber: EMK107B7474KA-T; ROHS Compliant?: YES; Tolerance: 10%; Vendor: Taiyo Yuden; size: 603
C37 C42 = CAP_NP: Comment: CAP CER 0.1UF 50V 5% C0G 0603; Comments: CAP CER 0.1UF 50V 5% C0G 0603; Lead Free?: YES; Manufacturer: Any; ROHS Compliant?: YES; Tolerance: 5%; Vendor: Any; size: 0603
C38 = CAPACITOR: Comment: CAP ALUM 22UF 10VDC 20% CODE-B; Comments: CAP ALUM 22UF 10VDC 20% CODE-B; Distributor: Any; Lead Free?: YES; Manufacturer: Panasonic; Manufacturer P/N: EEE-1AA220WR; Manufacturer_Part_Number: EEE-1AA220WR; Part number: EEE-1AA220WR; PartNumber: EEE-1AA220WR; ROHS Compliant?: YES; Rating: 10V; Tolerance: ±20%; VOLTAGE: 10V; Vendor: Any; size: Code B
C39 C44 C47 C50 C51 C54 = CAPACITOR_NON-POL: Comment: CAP CERAMIC 1UF 10V Y5V 0603; Comments: CAP CERAMIC 1UF 10V Y5V 0603; Digi-Key P/N: 311-1357-1-ND; Digikey P/N: 311-1357-1-ND; Distributor: Digi-Key; Distributor Part Number: 311-1357-1-ND; Distributor_Part_Number: 311-1357-1-ND; Lead Free?: YES; Manufacturer: Yageo; Manufacturer P/N: CC0603ZRY5V6BB105; Manufacturer_Part_Number: CC0603ZRY5V6BB105; Part number: CC0603ZRY5V6BB105; PartNumber: CC0603ZRY5V6BB105; ROHS Compliant?: YES; Rating: 10V; Tolerance: -20%, +80%; VOLTAGE: 10V; Vendor: Yageo; size: 603
C40 = CAP_NP: Comment: CAP CER 0.01UF 16V 10% X7R 0603; Comments: CAP CER 0.01UF 16V 10% X7R 0603; Lead Free?: YES; Manufacturer: Any; ROHS Compliant?: YES; Tolerance: 10%; Vendor: Any; size: 0603
C41 = CAP_NP: Comment: CAP CER 2.2UF 10V 10% X7R 0805; Comments: CAP CER 2.2UF 10V 10% X7R 0805; Lead Free?: YES; Manufacturer: Any; ROHS Compliant?: YES; Tolerance: 10%; Vendor: Any; size: 0805
D1 D3 D4 = LED_0: Comment: LED MINI TOPLED RED 630NM SMD; Comments: LED MINI TOPLED RED 630NM SMD; Digi-Key P/N: 475-2691-1-ND; Digikey P/N: 475-2691-1-ND; Distributor: Digi-Key; Distributor Part Number: Digi-Key; Distributor_Part_Number: 475-2691-1-ND; Lead Free?: YES; Manufacturer: OSRAM Opto Semiconductors Inc; Manufacturer P/N: LS M67K-J2L1-1-Z; Manufacturer_Part_Number: LS M67K-J2L1-1-Z; Part number: LS M67K-J2L1-1-Z; PartNumber: LS M67K-J2L1-1-Z; ROHS Compliant?: YES; Rating: 1.8V; VOLTAGE: 1.8V; Vendor: Osram Opto Semiconductors Inc; size: 805
D2 = 1SMB5922BTS: Comment: Diode, Zener, 7.5V, 50-mA, 3W; Comments: Diode, Zener, 7.5V, 50-mA, 3W; Manufacturer: On Semi; Manufacturer P/N: 1SMB5922BT3G
FB1 = BK1608HS600-T: Comment: Bead, Ferrite, SMT, 60Ohms, 800mA; Comments: Bead, Ferrite, SMT, 60Ohms, 800mA; Manufacturer: Taiyo Yuden
J2 J15 = HEADER_7X2: Comment: Do not populate
J4 = 4_HEADER
J5 = HEADER_2
J6 = USB_Conn_0: Comment: CONN MINI USB RCPT RA TYPE B SMD; Digikey P/N: A31727CT-ND; Manufacturer: TE Connectivity
Q1 = BSS138_1
R25 = R: Descriptiopn: RES 33K OHM 1/16W 5% 0402 SMD; Dig-Key P/N: 311-33KJRCT-ND; Part number: RC0402JR-0733KL
R26 = ERJ-1GE0R00C_2: Comments: RES 200 OHM 1/10W 5% 0603 SMD; Digi-Key P/N: P200GCT-ND; Distributor Part Number: P200GCT-ND; Lead Free?: YES; Manufacturer: Panasonic; Part number: ERJ-3GEYJ201V; RoHS Compliant?: YES; Vendor: Digi-Key; size: 603
R28-R31 R34 = ERJ-1GE0R00C_2: Comments: Resistor, Chip, 1/16W, 5%, 0402 SMD; Lead Free?: YES; Manufacturer: Any; RoHS Compliant?: YES; size: 0402
R32 = ERJ-1GE0R00C_2: Comments: Resistor, Chip, 1/16W, 5%, 0603 SMD; Lead Free?: YES; Manufacturer: Any; RoHS Compliant?: YES; size: 0603
S1 = EVQPSD02K
U3 = MSP430F5529_PN_80
U4 = TPD4E004DRY
U5 = TPS73533DRB_0
Y1 = ECS-240-20-5PX-TR: Comment: CRYSTAL 24.000MHZ 20PF SMD; Digikey P/N: XC1255CT-ND; Manufacturer: ECS Inc.
C45 = CAPACITOR: Comment: CAP TANT 47UF 10V 10% 1210; Comments: CAP TANT 47UF 10V 10% 1210; Digi-Key P/N: 478-1693-1-ND; Digikey P/N: 478-1693-1-ND; Distributor: Digi-Key; Distributor Part Number: 478-1693-1-ND; Distributor_Part_Number: 478-1693-1-ND; Lead Free?: YES; Manufacturer: AVX Corp; Manufacturer P/N: TAJB476K010RNJ; Manufacturer_Part_Number: TAJB476K010RNJ; Part number: TAJB476K010RNJ; PartNumber: TAJB476K010RNJ; ROHS Compliant?: YES; Rating: 10V; Tolerance: ±10%; VOLTAGE: 10V; Vendor: Digi-Key; size: 1210
C46 C49 C52 C53 = CAPACITOR: Comment: CAP TANTALUM 10UF 10V 20% SMD; Comments: CAP TANTALUM 10UF 10V 20% SMD; Digi-Key P/N: 478-3281-1-ND; Digikey P/N: 478-3281-1-ND; Distributor: Digi-Key; Distributor Part Number: 478-3281-1-ND; Distributor_Part_Number: 478-3281-1-ND; Lead Free?: YES; Manufacturer: AVX Corp; Manufacturer P/N: TAJP106M010RNJ; Manufacturer_Part_Number: TAJP106M010RNJ; Part number: TAJP106M010RNJ; PartNumber: TAJP106M010RNJ; ROHS Compliant?: YES; Rating: 10V; Tolerance: ±20%; VOLTAGE: 10V; Vendor: Digi-Key; size: 805
C48 = CAPACITOR: Comment: CAP TANT 22UF 16V 20% 2312; Comments: CAP TANT 22UF 16V 20% 2312; Digi-Key P/N: 478-4695-1-ND; Digikey P/N: 495-2245-2-ND; Distributor: Digi-Key; Distributor Part Number: 495-2245-2-ND; Distributor_Part_Number: 495-2245-2-ND; Lead Free?: YES; Manufacturer: Kemet; Manufacturer P/N: B45196H3226M309; Manufacturer_Part_Number: B45196H3226M309; Part number: B45196H3226M309; PartNumber: B45196H3226M309; ROHS Compliant?: YES; Rating: 10V; Tolerance: ±20%; VOLTAGE: 10V; Vendor: Digi-Key
J7 J12 = HEADER_5x2_SM_1: Comments: CONN HEADER VERT .100 10POS 15AU; Digi-Key P/N: A26573-ND; Distributor Part Number: A26573-ND; Lead Free?: YES; Manufacturer: Tyco; Part number: 87227-5; RoHS Compliant?: YES; Vendor: Digi-Key
J8 = HEADER_2: Comment: CONN HEADER VERT .100 2POS 15AU; Comments: CONN HEADER VERT .100 2POS 15AU; Digi-Key P/N: A26543-ND; Digikey P/N: A26543-ND; Distributor: Digi-Key; Distributor Part Number: A26543-ND; Distributor_Part_Number: A26543-ND; Lead Free?: YES; Manufacturer: TE Connectivity; Manufacturer P/N: 87224-2; Manufacturer_Part_Number: 87224-2; Part number: 87224-2; PartNumber: 87224-2; ROHS Compliant?: YES; Vendor: TE Connectivity
J9 = banana_jack_0
J10 J11 = banana_jack_0: Comment: POST BINDING ECON NYLON-INS RED; Comments: POST BINDING ECON NYLON-INS RED; Digi-Key P/N: 7006K-ND; Digikey P/N: 7006K-ND; Distributor: Digi-Key; Distributor Part Number: 7006K-ND; Distributor_Part_Number: 7006K-ND; Lead Free?: YES; Manufacturer: Keystone Electronics; Manufacturer P/N: 7006; Manufacturer_Part_Number: 7006; Part number: 7006; PartNumber: 7006; ROHS Compliant?: YES; Vendor: Keystone Electronics
J18 = DIP8_SOCKET
R33 = R: Descriptiopn: RES 4.7K OHM 1/10W 5% 0402 SMD; Dig-Key P/N: P4.7KJCT-ND; Part number: ERJ-2GEJ472X
R35 R36 = RESISTOR: Comment: RESISTOR .10 OHM 1/8W 1% 0402; Comments: RESISTOR .10 OHM 1/8W 1% 0402; Digi-Key P/N: P10KJTR-ND; Digikey P/N: P10KJTR-ND; Distributor: Digi-Key; Distributor Part Number: P.10AKCT-ND; Distributor_Part_Number: P.10AKCT-ND; Lead Free?: YES; Manufacturer: Panasonic - ECG; Manufacturer P/N: ERJ-2GEJ103X; Manufacturer_Part_Number: ERJ-2GEJ103X; Part Number: ERJ-2GEJ103X; PartNumber: ERJ-2GEJ103X; Power: 1/8W; ROHS Compliant?: Yes; Tolerance: 1%; Vendor: Digi-Key; size: 402
R37 = ERJ-1GE0R00C_2: Comments: RES 750 OHM 1/10W 5% 0603 SMD; Digi-Key P/N: P750GCT-ND; Distributor Part Number: P750GCT-ND; Lead Free?: YES; Manufacturer: Panasonic; Part number: ERJ-3GEYJ751V; RoHS Compliant?: YES; Vendor: Digi-Key; size: 603
R38 = ERJ-1GE0R00C_2: Comments: RES 360 OHM 1/10W 5% 0603 SMD; Digi-Key P/N: P360GCT-ND; Distributor Part Number: P360GCT-ND; Lead Free?: YES; Manufacturer: Panasonic; Part number: ERJ-3GEYJ361V; RoHS Compliant?: YES; Vendor: Digi-Key; size: 603
U6 = XTAL_OSC: Comment: OSCILLATOR 25.000 MHZ 2.5V SMD; Comments: OSCILLATOR 25.000 MHZ 2.5V SMD; Digi-Key P/N: 887-1442-1-ND; Digikey P/N: 887-1442-1-ND; Distributor: Digi-Key; Distributor Part Number: 887-1442-1-ND; Distributor_Part_Number: 887-1442-1-ND; Lead Free?: YES; Manufacturer: TXC CORPORATION; Manufacturer P/N: 7C-25.000MCB-T; Manufacturer_Part_Number: 7C-25.000MCB-T; Part number: 7C-25.000MCB-T; PartNumber: 7C-25.000MCB-T; ROHS Compliant?: YES; Vendor: TXC CORPORATION
U7 = TPS75725_0
J13 J14 = HEADER_10x2_SM
R39-R46 = R: Descriptiopn: RES 4.7 OHM 1/10W 5% 0402 SMD; Dig-Key P/N: P4.7JCT-ND; Part number: ERJ-2GEJ4R7X
U8 U9 = Molex_zQSFP_cage_0

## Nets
GND: C1.1 C2.1 C3.1 C4.1 C14.1 C15.1 C16.1 C17.1 C18.1 C28.1 C29.1 C30.2 C31.1 C32.1 C33.1 C34.2 C35.1 C36.1 C37.1 C38.2 C39.1 C40.1 C41.1 C42.1 C43.1 C44.1 C45.2 C46.2 C47.1 C48.2 C49.2 C50.2 C51.1 C52.2 C53.2 C54.1 C55.1 C56.1 D2.2(anode) J1.3(1) J1.4(2) J2.9 J4.1 J6.5(V-) J9.1 J13.1 J13.3 J13.5 J13.7 J13.9 J13.11 J13.13 J13.15 J13.17 J13.19 J14.1 J14.3 J14.5 J14.7 J14.9 J14.11 J14.13 J14.15 J14.17 J14.19 J15.2 J18.4 J25.1(3) J25.2(4) Q1.3(S) R7.1 R8.1 R19.1 R23.1 R27.1 R31.2 R32.1 R35.2 R37.2 R38.1 R47.1 R48.1 R49.1 R51.1 R53.1 R55.1 TP2.1 TP5.1 TP9.1 TP12.1 TP14.1 U1.A1(GND) U1.A2(GND) U1.A4(GND) U1.A6(GND) U1.A8(GND) U1.A10(GND) U1.A12(GND) U1.A14(GND) U1.A15(GND) U1.B2(GND) U1.B4(GND) U1.B6(GND) U1.B8(GND) U1.B10(GND) U1.B12(GND) U1.B14(GND) U1.C2(GND) U1.C3(GND) U1.C4(GND) U1.C5(GND) U1.C6(GND) U1.C7(GND) U1.C8(GND) U1.C9(GND) U1.C10(GND) U1.C11(GND) U1.C12(GND) U1.C13(GND) U1.C14(GND) U1.D1(GND) U1.D2(GND) U1.D4(RSVD5) U1.D5(GND) U1.D7(GND) U1.D9(GND) U1.D11(GND) U1.D12(RSVD2) U1.D14(GND) U1.D15(GND) U1.E4(RSVD4) U1.E11(GND) U1.F1(GND) U1.F2(GND) U1.F4(RSVD3) U1.F5(GND) U1.F7(GND) U1.F9(GND) U1.F11(GND) U1.F14(GND) U1.F15(GND) U1.G2(GND) U1.G3(GND) U1.G4(GND) U1.G5(GND) U1.G6(GND) U1.G7(GND) U1.G8(GND) U1.G9(GND) U1.G10(GND) U1.G11(GND) U1.G12(GND) U1.G13(GND) U1.G14(GND) U1.H2(GND) U1.H4(GND) U1.H6(GND) U1.H8(GND) U1.H10(GND) U1.H12(GND) U1.H14(GND) U1.J1(GND) U1.J2(GND) U1.J4(GND) U1.J6(GND) U1.J8(GND) U1.J10(GND) U1.J12(GND) U1.J14(GND) U1.J15(GND) U2.A1(GND) U2.A2(GND) U2.A4(GND) U2.A6(GND) U2.A8(GND) U2.A10(GND) U2.A12(GND) U2.A14(GND) U2.A15(GND) U2.B2(GND) U2.B4(GND) U2.B6(GND) U2.B8(GND) U2.B10(GND) U2.B12(GND) U2.B14(GND) U2.C2(GND) U2.C3(GND) U2.C4(GND) U2.C5(GND) U2.C6(GND) U2.C7(GND) U2.C8(GND) U2.C9(GND) U2.C10(GND) U2.C11(GND) U2.C12(GND) U2.C13(GND) U2.C14(GND) U2.D1(GND) U2.D2(GND) U2.D4(RSVD5) U2.D5(GND) U2.D7(GND) U2.D9(GND) U2.D11(GND) U2.D12(RSVD2) U2.D14(GND) U2.D15(GND) U2.E4(RSVD4) U2.E11(GND) U2.F1(GND) U2.F2(GND) U2.F4(RSVD3) U2.F5(GND) U2.F7(GND) U2.F9(GND) U2.F11(GND) U2.F14(GND) U2.F15(GND) U2.G2(GND) U2.G3(GND) U2.G4(GND) U2.G5(GND) U2.G6(GND) U2.G7(GND) U2.G8(GND) U2.G9(GND) U2.G10(GND) U2.G11(GND) U2.G12(GND) U2.G13(GND) U2.G14(GND) U2.H2(GND) U2.H4(GND) U2.H6(GND) U2.H8(GND) U2.H10(GND) U2.H12(GND) U2.H14(GND) U2.J1(GND) U2.J2(GND) U2.J4(GND) U2.J6(GND) U2.J8(GND) U2.J10(GND) U2.J12(GND) U2.J14(GND) U2.J15(GND) U3.14(AVSS1) U3.19(DVSS1) U3.49(DVSS2) U3.61(VSSU) U3.68(AVSS2) U4.3(GND) U5.4(GND) U5.9(PWPD) U6.2(GND) U7.3(GND) U7.6(EPAD) U8.C1(GND25) U8.C2(GND26) U8.C3(GND27) U8.C4(GND28) U8.C5(GND29) U8.C6(GND30) U8.C7(GND31) U8.C8(GND32) U8.C9(GND33) U8.C10(GND34) U8.C11(GND35) U8.C12(GND36) U8.C13(GND37) U8.L1(GND13) U8.L4(GND14) U8.L7(GND15) U8.L13(GND16) U8.L16(GND17) U8.L19(GND18) U8.L20(GND19) U8.L23(GND20) U8.L26(GND21) U8.L32(GND22) U8.L35(GND23) U8.L38(GND24) U8.U1(GND1) U8.U4(GND2) U8.U7(GND3) U8.U13(GND4) U8.U16(GND5) U8.U19(GND6) U8.U20(GND7) U8.U23(GND8) U8.U26(GND9) U8.U32(GND10) U8.U35(GND11) U8.U38(GND12) U9.C1(GND25) U9.C2(GND26) U9.C3(GND27) U9.C4(GND28) U9.C5(GND29) U9.C6(GND30) U9.C7(GND31) U9.C8(GND32) U9.C9(GND33) U9.C10(GND34) U9.C11(GND35) U9.C12(GND36) U9.C13(GND37) U9.L1(GND13) U9.L4(GND14) U9.L7(GND15) U9.L13(GND16) U9.L16(GND17) U9.L19(GND18) U9.L20(GND19) U9.L23(GND20) U9.L26(GND21) U9.L32(GND22) U9.L35(GND23) U9.L38(GND24) U9.U1(GND1) U9.U4(GND2) U9.U7(GND3) U9.U13(GND4) U9.U16(GND5) U9.U19(GND6) U9.U20(GND7) U9.U23(GND8) U9.U26(GND9) U9.U32(GND10) U9.U35(GND11) U9.U38(GND12)
V18: C42.2 U3.67(V18)
VBUS: C36.2 C38.1 D2.1(cathode) FB1.1 J6.1(V+) U3.65(VBUS) U4.6(VCC)
VDD_2p5V: C1.2 C2.2 C3.2 C4.2 C14.2 C15.2 C16.2 C17.2 C18.2 C28.2 C43.2 C49.1 C50.1 C55.2 C56.2 D4.1(ANODE) J11.1 J12.1 J12.3 J12.5 J12.7 J12.9 J18.8 R11.2 R12.1 R15.2 R22.2 R24.1 R33.2 R50.2 R52.2 R54.2 TP1.1 TP4.1 U1.D6(VDD) U1.D8(VDD) U1.D10(VDD) U1.E5(VDD) U1.E6(VDD) U1.E7(VDD) U1.E8(VDD) U1.E9(VDD) U1.E10(VDD) U1.F6(VDD) U1.F8(VDD) U1.F10(VDD) U2.D6(VDD) U2.D8(VDD) U2.D10(VDD) U2.E5(VDD) U2.E6(VDD) U2.E7(VDD) U2.E8(VDD) U2.E9(VDD) U2.E10(VDD) U2.F6(VDD) U2.F8(VDD) U2.F10(VDD) U6.4(VCC)
VDD_2p5V_PG#: R36.1 U7.5(PG#)
VDD_2p5V_REG: C45.1 J12.2 J12.4 J12.6 J12.8 J12.10 R36.2 U7.4(OUTPUT)
VDD_2p5V_REG_ENABLE#: J8.2 R35.1 U7.1(EN#)
VDD_3p3V: C44.2 C46.1 C47.2 C48.1 D3.1(ANODE) J7.1 J7.3 J7.5 J7.7 J7.9 J8.1 J10.1 TP10.1 U7.2(IN)
VDD_3p3V_USB: C33.2 C35.2 C41.2 D1.1(ANODE) R25.2 TP8.1 U3.11(AVCC1) U3.18(DVCC1) U3.50(DVCC2) U5.1(OUT)
ADDR0_1: R8.2 U1.D13(ADDR0)
ADDR0_2: R24.2 U2.D13(ADDR0)
ADDR1_1: R7.2 U1.E13(ADDR1)
ADDR1_2: R23.2 U2.E13(ADDR1)
AIN_B_0: J1.1(3) U3.1(P6.4/CB4/A4)
AIN_B_1: J1.2(4) U3.2(P6.5/CB5/A5)
ALL_DONE_N_1: J17.1 TP3.1 U1.D3(ALL_DONE_N)
ALL_DONE_N_2: TP15.1 U2.D3(ALL_DONE_N)
Bot_IntL_CABLE: J14.14 R43.1 U9.L28(Bot_IntL)
Bot_IntL_HOST: J13.14 R39.1 U8.L28(Bot_IntL)
Bot_LPMode_CABLE: J14.18 U9.L31(Bot_LPMode)
Bot_LPMode_HOST: J13.18 U8.L31(Bot_LPMode)
Bot_ModPrsL_CABLE: J14.12 J14.20 R44.1 U9.L27(Bot_ModPrsL)
Bot_ModPrsL_HOST: J13.12 J13.20 R40.1 U8.L27(Bot_ModPrsL)
Bot_ModSelL_CABLE: J14.16 U9.L8(Bot_ModSelL)
Bot_ModSelL_HOST: J13.16 U8.L8(Bot_ModSelL)
CAL_CLK_IN_1: R34.2 U1.E1(CAL_CLK_IN)
CAL_CLK_OUT_1: U1.E15(CAL_CLK_OUT) U2.E1(CAL_CLK_IN)
CAL_CLK_OUT_2: TP7.1 U2.E15(CAL_CLK_OUT)
DM: R28.2 U3.64(PU.1/DM)
DP: R29.2 R30.1 U3.62(PU.0/DP)
EN_SMB_1: J21.2 U1.E3(EN_SMB)
EN_SMB_2: J20.2 U2.E3(EN_SMB)
GPIO0_I2C_SDA: J3.4(2) U3.46(P4.1/PM_UCB1SIMO/PM_UCB1SDA)
GPIO1_I2C_SCL: J3.3(1) U3.47(P4.2/PM_UCB1SOMI/PM_UCB1SCL)
GPIO2_SPI_SCLK: J15.13 U3.45(P4.0/PM_UCB1STE/PM_UCA1CLK)
GPIO3_PWM2: J15.11 U3.33(P2.4/TA2.1)
GPIO4_UART_TXD: J15.9 U3.51(P4.4/PM_UCA1TXD/PM_UCA1SIMO)
GPIO5_UART_RXD: J15.7 U3.52(P4.5/PM_UCA1RXD/PM_UCA1SOMI)
GPIO6_PWM1: J15.5 U3.29(P2.0/TA1.1)
GPIO7_PWM0: J15.3 U3.23(P1.2/TA0.1)
GPIO8_ADC3: J15.1 U3.4(P6.7/CB7/A7)
GPIO9_ADC2: J15.14 U3.3(P6.6/CB6/A6)
GPIO10_VEREFn: J15.12 U3.10(P5.1/A9/VREF-/VEREF-)
GPIO11_VEREFp: C29.2 J15.10 U3.9(P5.0/A8/VREF+/VEREF+)
GPIO12_EFC0_CLOCK: J5.2 U3.21(P1.0/TA0CLK/ACLK)
INT_N: J5.1 R12.2 U1.F3(INT_N) U2.F3(INT_N)
P2_1: J15.8 U3.30(P2.1/TA1.2)
P2_3: J15.6 U3.32(P2.3/TA2.0)
P2_5: J15.4 U3.34(P2.5/TA2.2)
PUR: R30.2 R32.2 S1.1 S1.3 U3.63(PUR)
QSFP_ResetL_CABLE: J25.4(2) U9.L9(Bot_ResetL) U9.U9(Top_ResetL)
QSFP_ResetL_HOST: J25.3(1) U8.L9(Bot_ResetL) U8.U9(Top_ResetL)
QSFP_SCL_CABLE: J24.2(4) U9.L11(Bot_SCL) U9.U11(Top_SCL)
QSFP_SCL_HOST: J23.2(4) U8.L11(Bot_SCL) U8.U11(Top_SCL)
QSFP_SDA_CABLE: J24.1(3) U9.L12(Bot_SDA) U9.U12(Top_SDA)
QSFP_SDA_HOST: J23.1(3) U8.L12(Bot_SDA) U8.U12(Top_SDA)
QSFP_VCC_3P3V: C51.2 C52.1 C53.1 C54.2 J7.2 J7.4 J7.6 J7.8 J7.10 R39.2 R40.2 R41.2 R42.2 R43.2 R44.2 R45.2 R46.2 TP11.1 TP13.1 U8.L10(Bot_Vcc_Rx) U8.L29(Bot_Vcc_Tx) U8.L30(Bot_Vcc1) U8.U10(Top_Vcc_Rx) U8.U29(Top_Vcc_Tx) U8.U30(Top_Vcc1) U9.L10(Bot_Vcc_Rx) U9.L29(Bot_Vcc_Tx) U9.L30(Bot_Vcc1) U9.U10(Top_Vcc_Rx) U9.U29(Top_Vcc_Tx) U9.U30(Top_Vcc1)
READ_EN_N_1: J16.2 U1.F13(READ_EN_N)
READ_EN_N_2: J17.2 U2.F13(READ_EN_N)
RXN0_CABLE_BOT: U1.B1(RX7N) U9.L18(BotRx1n)
RXN0_CABLE_TOP: U1.A9(RX3N) U9.U18(Top_Rx1n)
RXN0_HOST_BOT: U2.B1(RX7N) U8.L18(BotRx1n)
RXN0_HOST_TOP: U2.A9(RX3N) U8.U18(Top_Rx1n)
RXN1_CABLE_BOT: U1.A5(RX5N) U9.L21(Bot_Rx2n)
RXN1_CABLE_TOP: U1.A13(RX1N) U9.U21(Top_Rx2n)
RXN1_HOST_BOT: U2.A5(RX5N) U8.L21(Bot_Rx2n)
RXN1_HOST_TOP: U2.A13(RX1N) U8.U21(Top_Rx2n)
RXN2_CABLE_BOT: U1.A3(RX6N) U9.L15(Bot_Rx3n)
RXN2_CABLE_TOP: U1.A11(RX2N) U9.U15(Top_Rx3n)
RXN2_HOST_BOT: U2.A3(RX6N) U8.L15(Bot_Rx3n)
RXN2_HOST_TOP: U2.A11(RX2N) U8.U15(Top_Rx3n)
RXN3_CABLE_BOT: U1.A7(RX4N) U9.L24(Bot_Rx4n)
RXN3_CABLE_TOP: U1.B15(RX0N) U9.U24(Top_Rx4n)
RXN3_HOST_BOT: U2.A7(RX4N) U8.L24(Bot_Rx4n)
RXN3_HOST_TOP: U2.B15(RX0N) U8.U24(Top_Rx4n)
RXP0_CABLE_BOT: U1.C1(RX7P) U9.L17(Bot_Rx1p)
RXP0_CABLE_TOP: U1.B9(RX3P) U9.U17(Top_Rx1p)
RXP0_HOST_BOT: U2.C1(RX7P) U8.L17(Bot_Rx1p)
RXP0_HOST_TOP: U2.B9(RX3P) U8.U17(Top_Rx1p)
RXP1_CABLE_BOT: U1.B5(RX5P) U9.L22(Bot_Rx2p)
RXP1_CABLE_TOP: U1.B13(RX1P) U9.U22(Top_Rx2p)
RXP1_HOST_BOT: U2.B5(RX5P) U8.L22(Bot_Rx2p)
RXP1_HOST_TOP: U2.B13(RX1P) U8.U22(Top_Rx2p)
RXP2_CABLE_BOT: U1.B3(RX6P) U9.L14(Bot_Rx3p)
RXP2_CABLE_TOP: U1.B11(RX2P) U9.U14(Top_Rx3p)
RXP2_HOST_BOT: U2.B3(RX6P) U8.L14(Bot_Rx3p)
RXP2_HOST_TOP: U2.B11(RX2P) U8.U14(Top_Rx3p)
RXP3_CABLE_BOT: U1.B7(RX4P) U9.L25(Bot_Rx4p)
RXP3_CABLE_TOP: U1.C15(RX0P) U9.U25(Top_Rx4p)
RXP3_HOST_BOT: U2.B7(RX4P) U8.L25(Bot_Rx4p)
RXP3_HOST_TOP: U2.C15(RX0P) U8.U25(Top_Rx4p)
SCL: J3.1(3) J4.3 J18.6 J22.4(2) J23.4(2) J24.4(2) U1.F12(SDC) U2.F12(SDC)
SDA: J3.2(4) J4.4 J18.5 J22.3(1) J23.3(1) J24.3(1) U1.E12(SDA) U2.E12(SDA)
Top_IntL_CABLE: J14.4 R45.1 U9.U28(Top_IntL)
Top_IntL_HOST: J13.4 R41.1 U8.U28(Top_IntL)
Top_LPMode_CABLE: J14.8 U9.U31(Top_LPMode)
Top_LPMode_HOST: J13.8 U8.U31(Top_LPMode)
Top_ModPrsL_CABLE: J14.2 J14.10 R46.1 U9.U27(Top_ModPrsL)
Top_ModPrsL_HOST: J13.2 J13.10 R42.1 U8.U27(Top_ModPrsL)
Top_ModSelL_CABLE: J14.6 U9.U8(Top_ModSelL)
Top_ModSelL_HOST: J13.6 U8.U8(Top_ModSelL)
TXN0_CABLE_BOT: U2.H1(TX7N) U9.L37(Bot_Tx1n)
TXN0_CABLE_TOP: U2.J9(TX3N) U9.U37(Top_Tx1n)
TXN0_HOST_BOT: U1.H1(TX7N) U8.L37(Bot_Tx1n)
TXN0_HOST_TOP: U1.J9(TX3N) U8.U37(Top_Tx1n)
TXN1_CABLE_BOT: U2.J5(TX5N) U9.L2(Bot_Tx2n)
TXN1_CABLE_TOP: U2.J13(TX1N) U9.U2(Top_Tx2n)
TXN1_HOST_BOT: U1.J5(TX5N) U8.L2(Bot_Tx2n)
TXN1_HOST_TOP: U1.J13(TX1N) U8.U2(Top_Tx2n)
TXN2_CABLE_BOT: U2.J3(TX6N) U9.L34(Bot_Tx3n)
TXN2_CABLE_TOP: U2.J11(TX2N) U9.U34(Top_Tx3n)
TXN2_HOST_BOT: U1.J3(TX6N) U8.L34(Bot_Tx3n)
TXN2_HOST_TOP: U1.J11(TX2N) U8.U34(Top_Tx3n)
TXN3_CABLE_BOT: U2.J7(TX4N) U9.L5(Bot_Tx4n)
TXN3_CABLE_TOP: U2.H15(TX0N) U9.U5(Top_Tx4n)
TXN3_HOST_BOT: U1.J7(TX4N) U8.L5(Bot_Tx4n)
TXN3_HOST_TOP: U1.H15(TX0N) U8.U5(Top_Tx4n)
TXP0_CABLE_BOT: U2.G1(TX7P) U9.L36(Bot_Tx1p)
TXP0_CABLE_TOP: U2.H9(TX3P) U9.U36(Top_Tx1p)
TXP0_HOST_BOT: U1.G1(TX7P) U8.L36(Bot_Tx1p)
TXP0_HOST_TOP: U1.H9(TX3P) U8.U36(Top_Tx1p)
TXP1_CABLE_BOT: U2.H5(TX5P) U9.L3(Bot_Tx2p)
TXP1_CABLE_TOP: U2.H13(TX1P) U9.U3(Top_Tx2p)
TXP1_HOST_BOT: U1.H5(TX5P) U8.L3(Bot_Tx2p)
TXP1_HOST_TOP: U1.H13(TX1P) U8.U3(Top_Tx2p)
TXP2_CABLE_BOT: U2.H3(TX6P) U9.L33(Bot_Tx3p)
TXP2_CABLE_TOP: U2.H11(TX2P) U9.U33(Top_Tx3p)
TXP2_HOST_BOT: U1.H3(TX6P) U8.L33(Bot_Tx3p)
TXP2_HOST_TOP: U1.H11(TX2P) U8.U33(Top_Tx3p)
TXP3_CABLE_BOT: U2.H7(TX4P) U9.L6(Bot_Tx4p)
TXP3_CABLE_TOP: U2.G15(TX0P) U9.U6(Top_Tx4p)
TXP3_HOST_BOT: U1.H7(TX4P) U8.L6(Bot_Tx4p)
TXP3_HOST_TOP: U1.G15(TX0P) U8.U6(Top_Tx4p)
VUSB: C37.2 S1.2 S1.4 U3.66(VUSB)
WP: J18.7 J19.2
N16780616: C32.2 U3.69(P5.2/XT2IN) Y1.1
N16780624: C31.2 U3.70(P5.3/XT2OUT) Y1.2
N16780665: J2.1 U3.72(PJ.0/TDO)
N16780674: Q1.1(G) U3.15(P8.0)
N16780676: J2.8 U3.71(TEST/SBWTCK)
N16780680: J2.3 U3.73(PJ.1/TDI/TCLK)
N16780690: J2.5 U3.74(PJ.2/TMS)
N16780698: J2.7 U3.75(PJ.3/TCK)
N16780708: C30.1 J2.11 R25.1 U3.76(*RST/NMI/SBWTDIO)
N16780744: D1.2(CATHODE) R26.1
N16780746: Q1.2(D) R26.2
N16780748: C34.1 U3.20(VCORE)
N16782035: J6.6(CASE1) J6.7(CASE2) J6.8(CASE3) J6.9(CASE4) R31.1
N16782058: J6.2(DM) R28.1 U4.1(IO1)
N16782064: J6.3(DP) R29.1 U4.4(IO3)
N16782665: C39.2 FB1.2 U5.5(EN) U5.8(IN)
N16782724: C40.2 U5.3(NR/FB)
N16869157: R33.1 U6.1(EOH)
N16869235: R34.1 U6.3(RF_Out)
N16899401: J16.1 R11.1
N16899406: J16.3 R19.2
N16899979: J17.3 R47.2
N16900523: J18.1 R49.2
N16900525: J18.2 R48.2
N16900527: J18.3 R27.2
N16901581: J19.1 R50.1
N16901585: J19.3 R51.2
N16901924: J20.1 R52.1
N16901939: J20.3 R53.2
N16902597: J21.1 R54.1
N16902612: J21.3 R55.2
N16903155: J22.2(4) R22.1
N16903160: J22.1(3) R15.1
N16904657: D3.2(CATHODE) R37.1
N16904658: D4.2(CATHODE) R38.2

Not connected (* = marked no-connect by the designer): J2 2* 4* 6* 10* 12* 13* 14*; J4 2*; J6 4(NC)* 10(CASE5)* 11(CASE6)*; U1 E2(RSVD0) E14(RSVD1); U2 E2(RSVD0) E14(RSVD1); U3 5(P7.0/CB8/A12)* 6(P7.1/CB9/A13)* 7(P7.2/CB10/A14)* 8(P7.3/CB11/A15)* 12(P5.4/XIN)* 13(P5.5/XOUT)* 16(P8.1)* 17(P8.2)* 22(P1.1/TA0.0)* 24(P1.3/TA0.2)* 25(P1.4/TA0.3)* 26(P1.5/TA0.4)* 27(P1.6/TA1CLK/CBOUT)* 28(P1.7/TA1.0)* 31(P2.2/TA2CLK/SMCLK)* 35(P2.6/RTCCLK/DMAE0)* 36(P2.7/UCB0STE/UCA0CLK)* 37(P3.0/UCB0SIMO/UCB0SDA)* 38(P3.1/UCB0SOMI/UCB0SCL)* 39(P3.2/UCB0CLK/UCA0STE)* 40(P3.3/UCA0TXD/UCA0SIMO)* 41(P3.4/UCA0RXD/UCA0SOMI)* 42(P3.5/TB0.5)* 43(P3.6/TB0.6)* 44(P3.7/TB0OUTH/SVMOUT)* 48(P4.3/PM_UCB1CLK/PM_UCA1STE)* 53(P4.6/PM_NONE)* 54(P4.7/PM_NONE)* 55(P5.6/TB0.0)* 56(P5.7/TB0.1)* 57(P7.4/TB0.2)* 58(P7.5/TB0.3)* 59(P7.6/TB0.4)* 60(P7.7/TB0CLK/MCLK)* 77(P6.0/CB0/A0)* 78(P6.1/CB1/A1)* 79(P6.2/CB2/A2)* 80(P6.3/CB3/A3)*; U4 2(IO2)* 5(IO4)*; U5 2(NC1)* 6(NC2)* 7(NC3)*

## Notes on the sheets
sheet 1
- DS280BR810 QSFP Reference Design
- Datapath Solutions
  Texas Instruments, Inc.
sheet 2
- 1st DS280BR810
- Layout: All differential traces are to be routed with 100 ohm differential impedance
- SMBUS Slave Mode
  ADDR0=1KOHMs to GND
  ADDR1=1KOHMs to GND
- LAYOUT NOTE: Layout bypass
  caps close to DUT
- Layout Notes: Place the below two test points close to the Chip
- Datapath Solutions
  Texas Instruments, Inc.
sheet 3
- 2nd DS280BR810
- Layout: All differential traces are to be routed with 100 ohm differential impedance
- SMBUS Slave Mode
  ADDR0=1KOHMs to VDD
  ADDR1=1KOHMs to GND
- LAYOUT NOTE: Layout bypass
  caps close to DUT
- Layout Notes: Place the below two test points close to the Chip
- Datapath Solutions
  Texas Instruments, Inc.
sheet 4
- TI USB2ANY
- GPIOs from/to MSP430
- ASSEMBLY
  NOTE: Do not
  populate
- SILKSCREEN:
  MSP I2C        MAIN I2C
- SILKSCREEN:
  GND
  SCL
  SDA
- SILKSCREEN:
  INT_N to MSP430
- SILKSCREEN:
  3.3V (MSP)
- SILKSCREEN:
  GND
- Datapath Solutions
  Texas Instruments, Inc.
- Datapath Solutions
  Texas Instruments, Inc.
sheet 5
- CLOCK AND POWER
- EEPROM SOCKET
- LAYOUT NOTE:
  Layout bypass cap
  close to
  oscillator.
- 2.5V SUPPLY REGULATOR, 3A MAX (INCLUDING BYPASS OPTION)
- SILKSCREEN:
  2.5V regulator disable.
  Install jumper before
  supplying 2.5V externally.
- SILKSCREEN:
  GND
- Power binding posts should be 750mil apart
- LAYOUT NOTE: Place
  1uF capacitor as
  close as possible
  to the input pin.
- 3.3V SUPPLY
- Power binding posts should be 750mil apart
- SILK:
  3.3V
- SILKSCREEN:
  VDD_3p3V
- Power binding posts should
  be 750mil apart
- SILKSCREEN:
  VDD_2p5V
- SILKSCREEN:
  3.3V Power
- LAYOUT NOTE: Place LED near
  3.3V banana jack (J14)
- SILKSCREEN:
  2.5V Power
- LAYOUT NOTE:
  Place LED near
  2.5V banana
  jack
- SILKSCREEN:
  Connect 2.5V Reg
  output to main 2.5V
  plane
- LAYOUT NOTE:
  Bulk supply
  decoupling
  close to banana
  jack.
- LAYOUT NOTE: This header
  connects two power planes:
  the main 2.5V plane and
  the regulator's output
  plane.
- Datapath Solutions
  Texas Instruments, Inc.
- Datapath Solutions
  Texas Instruments, Inc.
sheet 6
- QSFP28 HOST SIDE
- SILKSCREEN:
  QSFP_VCC_3P3V
- SILKSCREEN:
  GND
- QSFP OBSERVATION AND
  CONTROL HEADER
- SILKSCREEN:
  QSFP ResetL
- Datapath Solutions
  Texas Instruments, Inc.
sheet 7
- QSFP28 Cable SIDE
- SILKSCREEN:
  QSFP_VCC_3P3V
- SILKSCREEN:
  GND
- QSFP OBSERVATION AND
  CONTROL HEADER
- Datapath Solutions
  Texas Instruments, Inc.
